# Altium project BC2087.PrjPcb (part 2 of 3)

## Sheet BOOT_JTAG_AUX.SchDoc: =project_title
size Tabloid; CompanyName: Luxonis Holding; DrawnBy: Boris Chou / Blaz Kvas; Organization: Luxonis Holding; Address1: 1925 Harmony Park Drive; Address2: Westminster, CO; Address3: 80234; Address4: United States; DocumentNumber: D2088000; Revision: R1M1E1; SheetNumber: 9; SheetTotal: 12
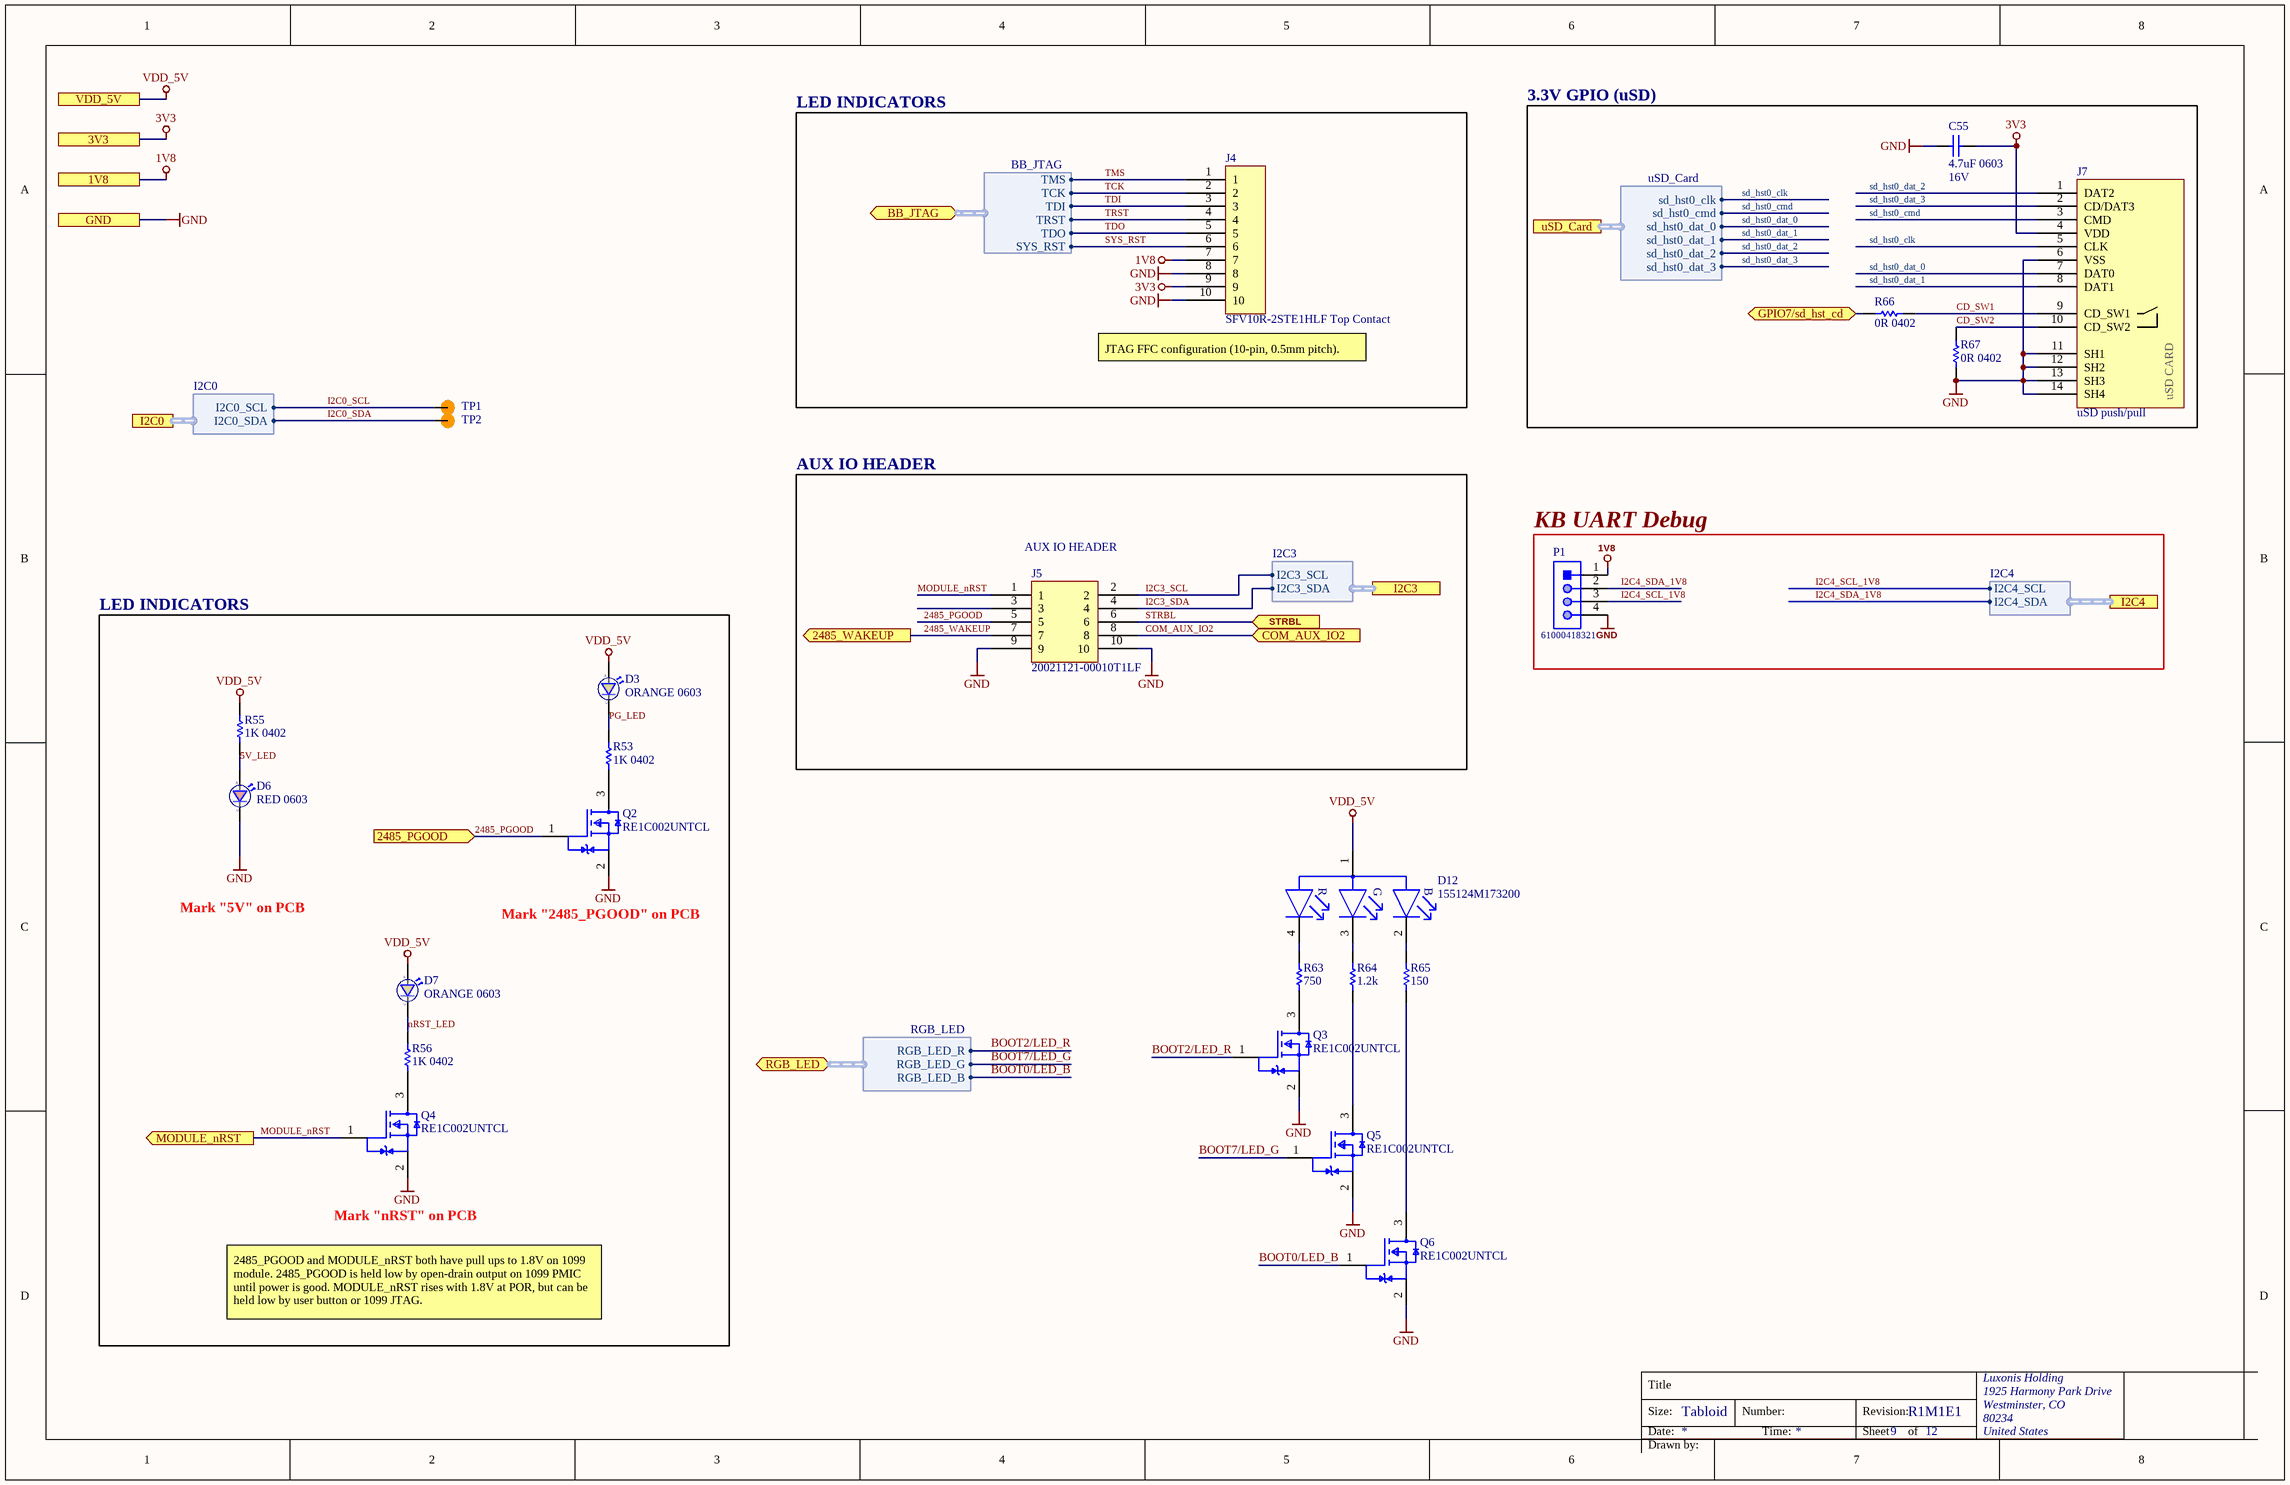
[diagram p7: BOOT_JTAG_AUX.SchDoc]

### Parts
C55  4.7uF 0603  Voltage Rating: 16V  [CAPC0603(1608)100_N]
D3  ORANGE 0603  [SML_D1xx8W]
D6  RED 0603  [SML_D1xx8W]
D7  ORANGE 0603  [SML_D1xx8W]
D12  155124M173200  [FP-155124M173200-MFG]
J4  SFV10R-2STE1HLF Top Contact  [SFV10R-2STE1HLF]
J5  20021121-00010T1LF  [20021121-00010T1LF]
J7  uSD push/pull  [104031-0811]
P1  61000418321  [61000418321]
Q2  RE1C002UNTCL  [RE1C002UNTCL]
Q3  RE1C002UNTCL  [RE1C002UNTCL]
Q4  RE1C002UNTCL  [RE1C002UNTCL]
Q5  RE1C002UNTCL  [RE1C002UNTCL]
Q6  RE1C002UNTCL  [RE1C002UNTCL]
R53  1K 0402  [RESC0402(1005)_N]
R55  1K 0402  [RESC0402(1005)_N]
R56  1K 0402  [RESC0402(1005)_N]
R63  value 750  [RESC1005X40X25NL05T05]  (hidden comment: ERJ2RKF7500X)
R64  value 1.2k  [RESC1005X40X25NL05T05]  (hidden comment: CRCW04021K20FKED)
R65  value 150  [RESC1005X40X25NL05T10]  (hidden comment: RC0402FR-07150RL)
R66  0R 0402  [RESC0402(1005)_N]
R67  0R 0402  [RESC0402(1005)_N]
TP1  TP100_200_NS  [TP100_200_NS]  (value not drawn)  (no BOM)
TP2  TP100_200_NS  [TP100_200_NS]  (value not drawn)  (no BOM)

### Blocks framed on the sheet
LED INDICATORS: J4
3.3V GPIO (uSD): C55 J7 R66 R67
AUX IO HEADER: J5
KB UART Debug: P1
LED INDICATORS: D3 D6 D7 Q2 Q4 R53 R55 R56

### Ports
1V8, 3V3, 2485_PGOOD (in), 2485_WAKEUP (out), BB_JTAG (bidir, harness BB_JTAG), COM_AUX_IO2 (in), GND, GPIO7/sd_hst_cd (bidir), I2C0 (harness I2C0), I2C3 (harness I2C3), I2C4 (harness I2C4), MODULE_nRST (out), RGB_LED (bidir, harness RGB_LED), STRBL (in), uSD_Card (harness uSD_Card), VDD_5V

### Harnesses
BB_JTAG: TMS, TCK, TDI, TRST, TDO, SYS_RST
I2C3: I2C3_SDA, I2C3_SCL
uSD_Card: sd_hst0_clk, sd_hst0_cmd, sd_hst0_dat_0, sd_hst0_dat_1, sd_hst0_dat_2, sd_hst0_dat_3
I2C0: I2C0_SDA, I2C0_SCL
RGB_LED: RGB_LED_G, RGB_LED_B, RGB_LED_R
I2C4: I2C4_SDA, I2C4_SCL

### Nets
1V8: J4.7 P1.1 ; port 1V8
3V3: C55.2 J4.9 J7.4(VDD) ; port 3V3
GND: C55.1 D6.1(C) J4.8 J4.10 J5.9 J5.10 J7.6(VSS) J7.11(SH1) J7.12(SH2) J7.13(SH3) J7.14(SH4) P1.4 Q2.2(Source) Q3.2(Source) Q4.2(Source) Q5.2(Source) Q6.2(Source) R67.1 ; port GND
VDD_5V: D3.2(A) D7.2(A) D12.1(COMMON_ANODE) R55.2 ; port VDD_5V
5V_LED: D6.2(A) R55.1
2485_PGOOD: J5.5 Q2.1(Gate) ; port 2485_PGOOD
2485_WAKEUP: J5.7 ; port 2485_WAKEUP
BOOT0/LED_B: Q6.1(Gate) ; port RGB_LED.RGB_LED_B
BOOT2/LED_R: Q3.1(Gate) ; port RGB_LED.RGB_LED_R
BOOT7/LED_G: Q5.1(Gate) ; port RGB_LED.RGB_LED_G
CD_SW1: J7.9(CD_SW1) R66.1
CD_SW2: J7.10(CD_SW2) R67.2
COM_AUX_IO2: J5.8 ; port COM_AUX_IO2
GPIO7/sd_hst_cd: R66.2 ; port GPIO7/sd_hst_cd
I2C0_SCL: TP1.1 ; port I2C0.I2C0_SCL
I2C0_SDA: TP2.1 ; port I2C0.I2C0_SDA
I2C3_SCL: J5.2 ; port I2C3.I2C3_SCL
I2C3_SDA: J5.4 ; port I2C3.I2C3_SDA
I2C4_SCL_1V8: P1.3 ; port I2C4.I2C4_SCL
I2C4_SDA_1V8: P1.2 ; port I2C4.I2C4_SDA
MODULE_nRST: J5.1 Q4.1(Gate) ; port MODULE_nRST
nRST_LED: D7.1(C) R56.2
PG_LED: D3.1(C) R53.2
sd_hst0_clk: J7.5(CLK) ; port uSD_Card.sd_hst0_clk
sd_hst0_cmd: J7.3(CMD) ; port uSD_Card.sd_hst0_cmd
sd_hst0_dat_0: J7.7(DAT0) ; port uSD_Card.sd_hst0_dat_0
sd_hst0_dat_1: J7.8(DAT1) ; port uSD_Card.sd_hst0_dat_1
sd_hst0_dat_2: J7.1(DAT2) ; port uSD_Card.sd_hst0_dat_2
sd_hst0_dat_3: J7.2(CD/DAT3) ; port uSD_Card.sd_hst0_dat_3
STRBL: J5.6 ; port STRBL
SYS_RST: J4.6 ; port BB_JTAG.SYS_RST
TCK: J4.2 ; port BB_JTAG.TCK
TDI: J4.3 ; port BB_JTAG.TDI
TDO: J4.5 ; port BB_JTAG.TDO
TMS: J4.1 ; port BB_JTAG.TMS
TRST: J4.4 ; port BB_JTAG.TRST
NetD12_2: D12.2(BLUE_C) R65.2
NetD12_3: D12.3(GREEN_C) R64.2
NetD12_4: D12.4(RED_C) R63.2
NetQ2_3: Q2.3(Drain) R53.1
NetQ3_3: Q3.3(Drain) R63.1
NetQ4_3: Q4.3(Drain) R56.1
NetQ5_3: Q5.3(Drain) R64.1
NetQ6_3: Q6.3(Drain) R65.1

Not connected (* = marked no-connect by the designer): J5 3

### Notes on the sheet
- (near J4) JTAG FFC configuration (10-pin, 0.5mm pitch).
- (near J5) AUX IO HEADER
- Mark "5V" on PCB
- Mark "2485_PGOOD" on PCB
- Mark "nRST" on PCB
- 2485_PGOOD and MODULE_nRST both have pull ups to 1.8V on 1099 module. 2485_PGOOD is held low by open-drain output on 1099 PMIC until power is good. MODULE_nRST rises with 1.8V at POR, but can be held low by user button or 1099 JTAG.

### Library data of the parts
C55 = GRM188R61C475KAAJD: CAP CER 4.7UF 16V X5R 0603 10%; Manufacturer 1: Murata; Material: Ceramic
D3 D7 = SML-D12D8WT86: LED ORANGE DIFFUSED 0603 SMD Orange 605nm LED Indication - Discrete 2.2V 0603 (1608 Metric); Manufacturer 1: Rohm; Lens Color: White; Lens Style: Diffused,Colorless,Rectangular; Number of LEDs: 1; Viewing Angle: 160°; Forward Current: 20mA; Luminous Intensity: 100mcd
D6 = SML-D12U8WT86: LED RED DIFFUSED 0603 SMD Red 620nm LED Indication - Discrete 2.2V 0603 (1608 Metric); Manufacturer 1: Rohm; Lens Color: White,Clear,Diffused; Lens Style: Rectangular,Diffused,Colorless; Forward Current: 20mA; Luminous Intensity: 63mcd; Number of LEDs: 1; Viewing Angle: 160°
D12 = CMP-007-00038-1: Triple Color LED; Manufacturer 1: Wurth Elektronik; Max Current Rating: 30mA; Viewing Angle: 120°; Colour: RGB; Lens Style: Side lens; Forward Current: 20mA
J4 = SFV10R-2STE1HLF: CONN FFC TOP 10POS 0.50MM R/A; Manufacturer 1: Amphenol FCI; Actuator Material: Glass,Polyphenylene; Number of Contacts: 10; Current Rating: 500mA; Voltage Rating: 50V; Contact Resistance: 30mR; Insulation Resistance: 100MR; Gender: Female; Wire/Cable Type: Straight; Pitch: 0.5mm; System: Connector
J5 = 20021121-00010T1LF: CONN HEADER SMD 10POS 1.27MM; Manufacturer 1: Amphenol FCI; Number of Contacts: 10; Contact Resistance: 30mR; Max Voltage Rating (AC): 125V; Connector Type: Male Pin; Row Spacing: 0.05inch
J7 = 104031-0811: CONN MICRO SD CARD PUSH-PULL R/A; Manufacturer 1: Molex
P1 = CMP-002-00148-1: Terminal and Terminal Block; Manufacturer 1: Wurth Elektronik; Connector Type: BOARD CONNECTOR
Q2-Q6 = RE1C002UNTCL: MOSFET N-CH 20V 0.2A EMT3; Manufacturer 1: Rohm; Continuous Drain Current (ID): 200mA; Rds On Max: 1.2R; Input Capacitance: 25pF; Max Power Dissipation: 150mW
R53 R55 R56 = RC0402FR-071KL: RES SMD 1K OHM 1% 1/16W 0402 1 kOhms ±1% 0.063W, 1/16W Chip Resistor 0402 (1005 Metric) Moisture Resistant Thick Film; Manufacturer 1: Yageo; Temperature Coefficient: 100ppm/°C; Power Rating: 62.5mW; Voltage Rating (DC): 50V; Resistance: 1kR
R63 = CMP-009-00197-1: Fixed Resistor, Metal Glaze/thick Film, 0.1W, 750ohm, 50V, 1% +/-Tol, 100ppm/Cel, Surface Mount, 0402; Manufacturer 1: Panasonic; Power: 100mW
R64 = CMP-009-00198-1: Fixed Resistor, Metal Glaze/thick Film, 0.063W, 1200ohm, 50V, 1% +/-Tol, 100ppm/Cel, Surface Mount, 0402; Manufacturer 1: Vishay; Power: 63mW
R65 = CMP-009-00196-1: Fixed Resistor, Metal Glaze/thick Film, 0.0625W, 150ohm, 50V, 1% +/-Tol, 100ppm/Cel, Surface Mount, 0402; Manufacturer 1: Yageo
R66 R67 = CRCW04020000Z0ED: RES SMD 0 OHM JUMPER 1/16W 0402; Manufacturer 1: Vishay; Resistance: 0mR; Power Rating: 63mW; Voltage Rating: 50V; Temperature Coefficient: 100ppm/°C; Tolerance: 5%
TP1 TP2 = TEST_POINT

## Sheet PoE_Si3404.SchDoc: =project_title
size Tabloid; CompanyName: Luxonis Holding; DrawnBy: Boris Chou / Blaz Kvas; Organization: Luxonis Holding; Address1: 1925 Harmony Park Drive; Address2: Westminster, CO; Address3: 80234; Address4: United States; DocumentNumber: D2088000; Revision: R1M1E1; SheetNumber: 3; SheetTotal: 12
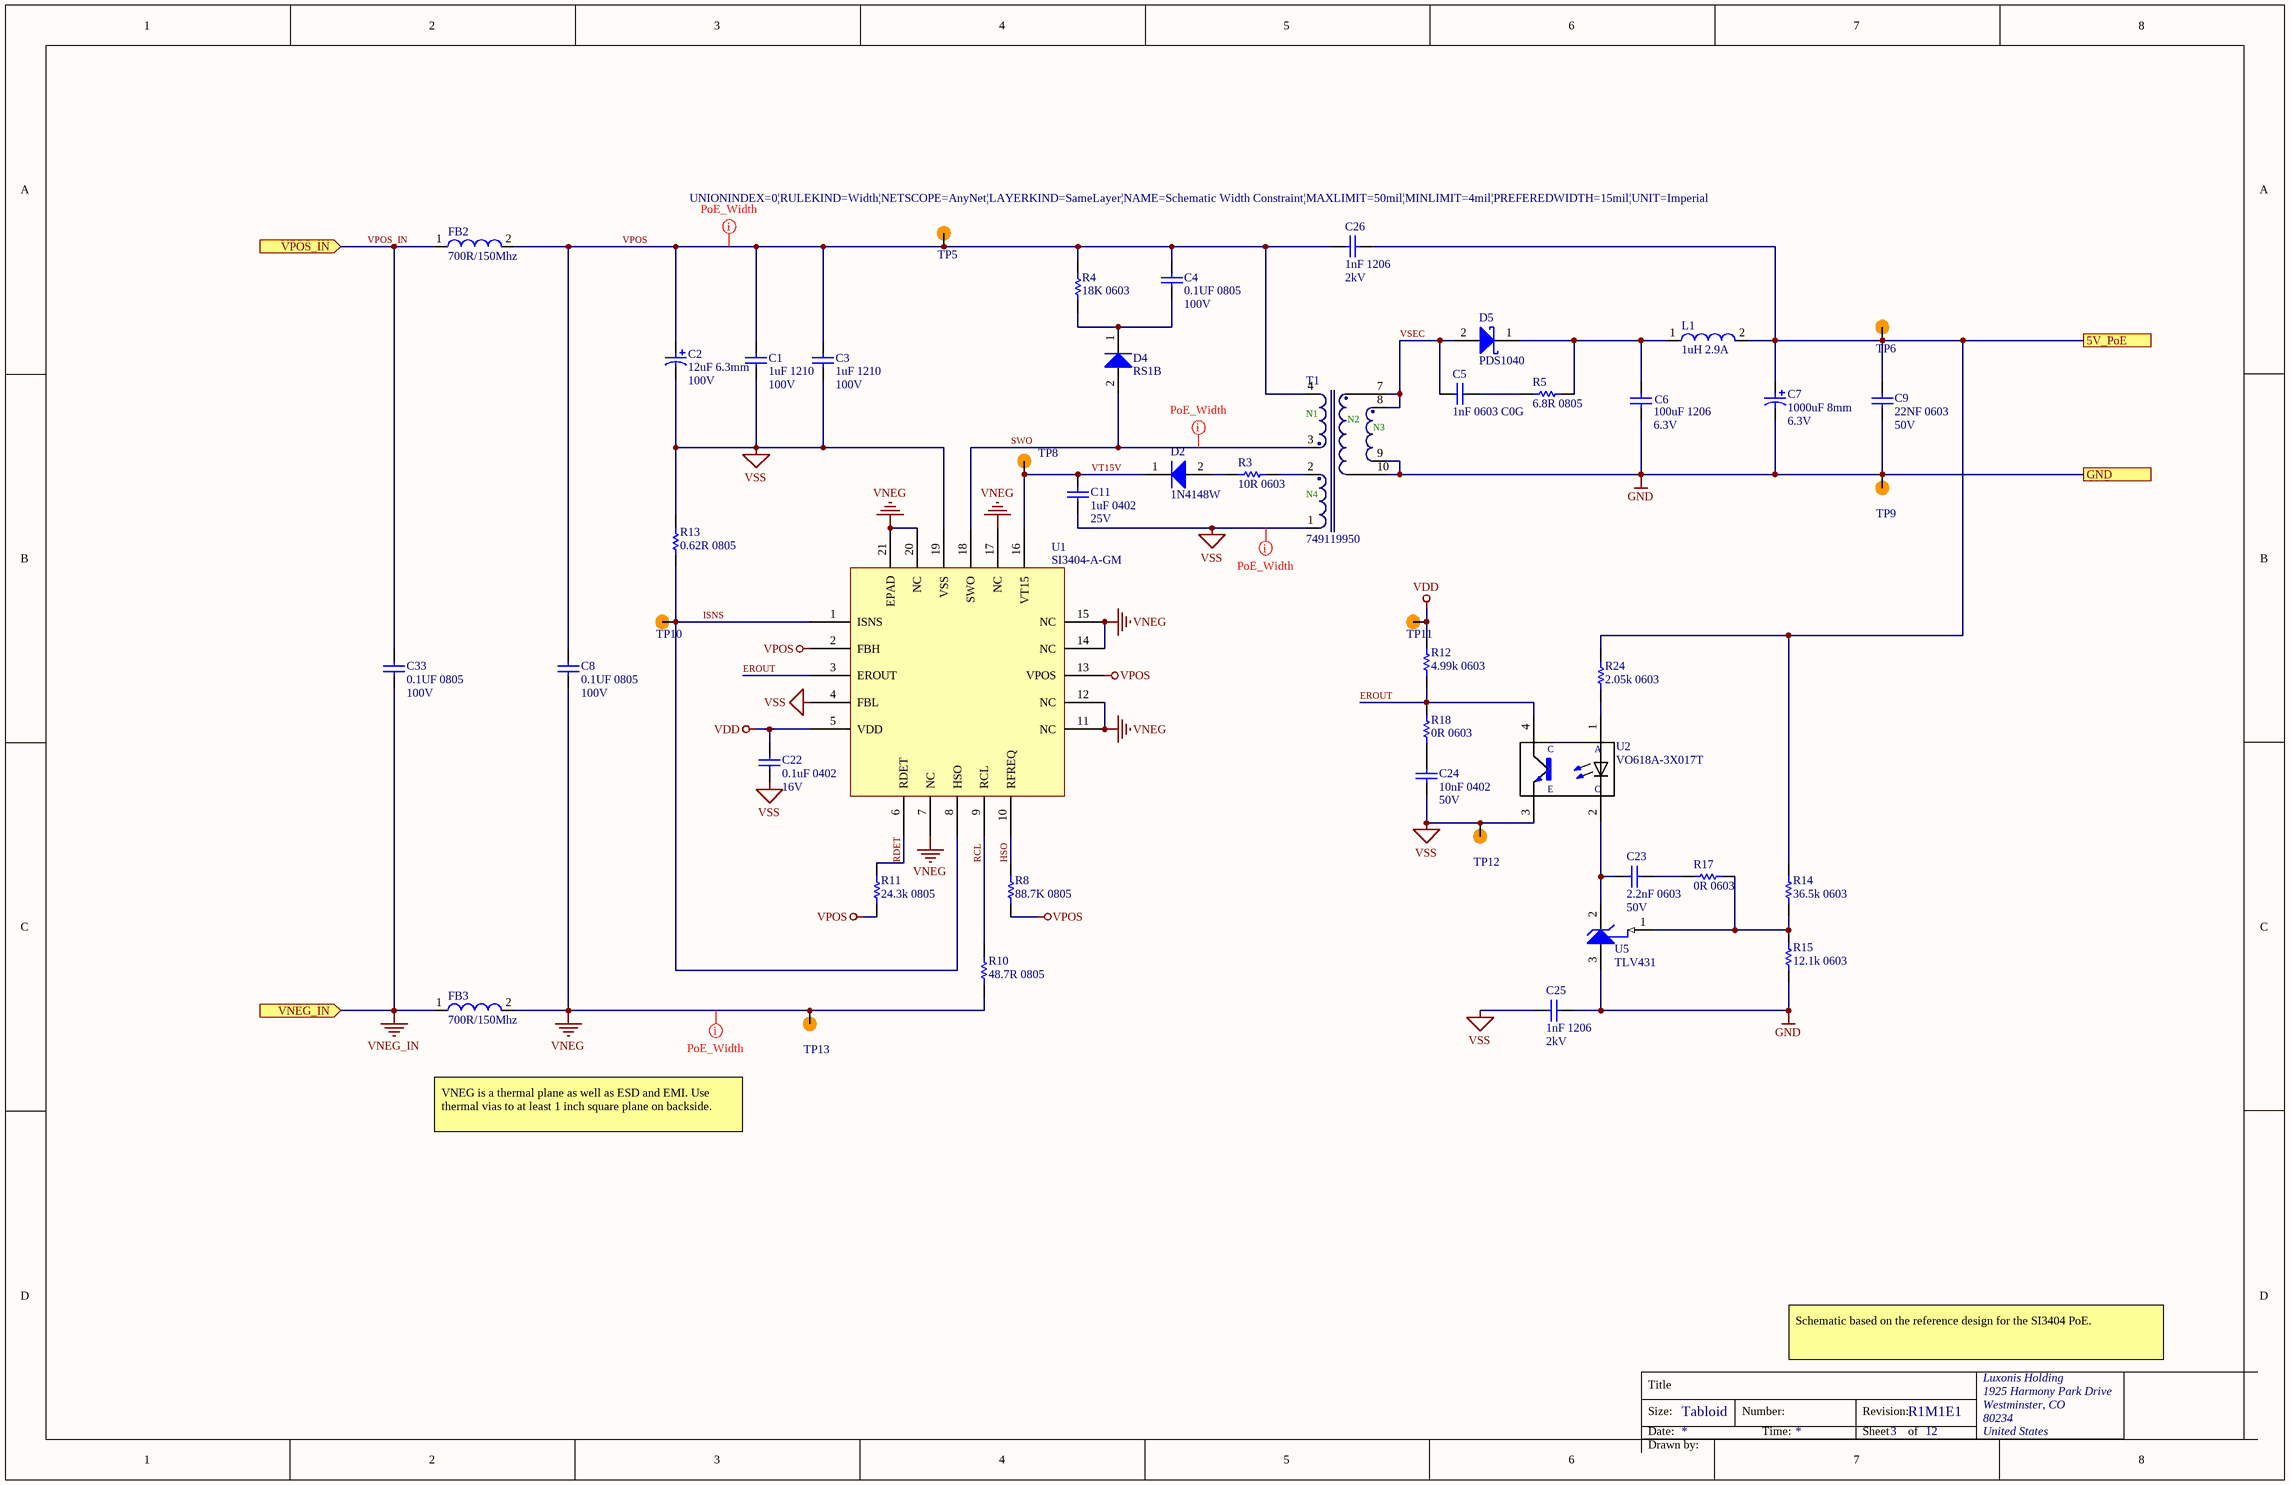
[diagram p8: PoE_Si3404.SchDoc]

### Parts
C1  1uF 1210  Voltage Rating: 100V  [CAPC1210(3225)280_N]
C2  12uF 6.3mm  Voltage: 100V  [EEU-FC2A120]
C3  1uF 1210  Voltage Rating: 100V  [CAPC1210(3225)280_N]
C4  0.1UF 0805  Voltage Rating: 100V  [CAPC0805(2012)145_N]
C5  1nF 0603 C0G  [CAPC0603(1608)100_N]
C6  100uF 1206  Voltage: 6.3V  [CAPC1206(3216)190_N]
C7  1000uF 8mm  Voltage: 6.3V  [ECA-0JM102]
C8  0.1UF 0805  Voltage Rating: 100V  [CAPC0805(2012)145_N]
C9  22NF 0603  Voltage: 50V  [CAPC0603(1608)100_N]
C11  1uF 0402  Voltage Rating: 25V  [CAPC0402(1005)70_N]
C22  0.1uF 0402  Voltage Rating: 16V  [CAPC0402(1005)60_N]
C23  2.2nF 0603  Voltage: 50V  [CAPC0603(1608)100_N]
C24  10nF 0402  Voltage Rating: 50V  [CAPC0402(1005)60_N]
C25  1nF 1206  Voltage Rating (DC): 2kV  [CAPC1206(3216)190_N]
C26  1nF 1206  Voltage Rating (DC): 2kV  [CAPC1206(3216)190_N]
C33  0.1UF 0805  Voltage Rating: 100V  [CAPC0805(2012)145_N]
D2  1N4148W  [1N4148W-7-F]
D4  RS1B  [RS1B]
D5  PDS1040  [PDS1040-13]
FB2  700R/150Mhz  [742792040]
FB3  700R/150Mhz  [742792040]
L1  1uH 2.9A  [DO1608C-102MLx]
R3  10R 0603  [RESC0603(1608)_N]
R4  18K 0603  [RESC0603(1608)_N]
R5  6.8R 0805  [RESC0805(2012)_N]
R8  88.7K 0805  [RESC0805(2012)_N]
R10  48.7R 0805  [RESC0805(2012)_N]
R11  24.3k 0805  [RESC0805(2012)_N]
R12  4.99k 0603  [RESC0603(1608)_N]
R13  0.62R 0805  [RESC0805(2012)_N]
R14  36.5k 0603  [RESC0603(1608)_N]
R15  12.1k 0603  [RESC0603(1608)_N]
R17  0R 0603  [RESC0603(1608)_N]
R18  0R 0603  [RESC0603(1608)_N]
R24  2.05k 0603  [RESC0603(1608)_N]
T1  749119950  [749119950]
TP5  TP100_200_NS  [TP100_200_NS]  (value not drawn)  (no BOM)
TP6  TP100_200_NS  [TP100_200_NS]  (value not drawn)  (no BOM)
TP8  TP100_200_NS  [TP100_200_NS]  (value not drawn)  (no BOM)
TP9  TP100_200_NS  [TP100_200_NS]  (value not drawn)  (no BOM)
TP10  TP100_200_NS  [TP100_200_NS]  (value not drawn)  (no BOM)
TP11  TP100_200_NS  [TP100_200_NS]  (value not drawn)  (no BOM)
TP12  TP100_200_NS  [TP100_200_NS]  (value not drawn)  (no BOM)
TP13  TP100_200_NS  [TP100_200_NS]  (value not drawn)  (no BOM)
U1  SI3404-A-GM  [Si3404-A-GM]
U2  VO618A-3X017T  [VO618A-3X017T]
U5  TLV431  [TLV431BCDBZR]

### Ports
5V_PoE, GND, VNEG_IN (in), VPOS_IN (in)

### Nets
5V_PoE: C7.1 C9.2 C26.2 L1.2 R14.2 R24.2 TP6.1 ; port 5V_PoE
GND: C6.1 C7.2 C9.1 C25.2 R15.1 T1.9 T1.10 TP9.1 U5.3(ANODE) ; port GND
VDD: C22.2 R12.2 TP11.1 U1.5(VDD)
VNEG: C8.1 FB3.2 R10.1 TP13.1 U1.7(NC) U1.11(NC) U1.12(NC) U1.14(NC) U1.15(NC) U1.17(NC) U1.20(NC) U1.21(EPAD)
VNEG_IN: C33.1 FB3.1 ; port VNEG_IN
VPOS: C1.2 C2.1 C3.2 C4.2 C8.2 C26.1 FB2.2 R4.2 R8.1 R11.1 T1.4 TP5.1 U1.2(FBH) U1.13(VPOS)
VSS: C1.1 C2.2 C3.1 C11.1 C22.1 C24.1 C25.1 R13.2 T1.1 TP12.1 U1.4(FBL) U1.19(VSS) U2.3(E)
EROUT: R12.1 R18.2 U1.3(EROUT) U2.4(CO)
HSO: R8.2 U1.10(RFREQ)
ISNS: R13.1 TP10.1 U1.1(ISNS) U1.8(HSO)
RCL: R10.2 U1.9(RCL)
RDET: R11.2 U1.6(RDET)
SWO: D4.2(A) T1.3 U1.18(SWO)
VPOS_IN: C33.2 FB2.1 ; port VPOS_IN
VSEC: C5.2 D5.2(A) T1.7 T1.8
VT15V: C11.2 D2.1(K) TP8.1 U1.16(VT15)
NetC4_1: C4.1 D4.1(K) R4.1
NetC5_1: C5.1 R5.1
NetC6_2: C6.2 D5.1(K) L1.1 R5.2
NetC23_1: C23.1 U2.2(C) U5.2(CATHODE)
NetC23_2: C23.2 R17.2
NetC24_2: C24.2 R18.1
NetD2_2: D2.2(A) R3.1
NetR3_2: R3.2 T1.2
NetR14_1: R14.1 R15.2 R17.1 U5.1(REF)
NetR24_1: R24.1 U2.1(A)

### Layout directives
rule Width Constraint [Pref Width = 15mil    Min Width = 4mil    Max Width = 50mil]; net class PoE: SWO, VNEG, VPOS, VSS

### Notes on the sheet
- VNEG is a thermal plane as well as ESD and EMI. Use thermal vias to at least 1 inch square plane on backside.
- Schematic based on the reference design for the SI3404 PoE.

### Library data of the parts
C1 C3 = CL32B105KCJNNNE: CAP CER 1UF 100V X7R 1210; Manufacturer 1: Samsung; Tolerance: 10%
C2 = EEU-FC2A120: CAP ALUM 12UF 20% 100V RADIAL; Manufacturer 1: Panasonic; Lead/Base Style: Straight; Ripple Current: 114mA; Life (Hours): 1000Hour; ESR (Equivalent Series Resistance): 1.8R; Leakage Current: 3uA; Dissipation Factor: 0.07%; Polarity: Polar; Lead Diameter: 0.5mm
C4 C8 C33 = CL21B104KCFNNNE: CAP CER 0.1UF 100V X7R 0805; Manufacturer 1: Samsung; Tolerance: 10%; Capacitance: 100nF
C5 = GRM1885C1H102FA01D: CAP CER 1000PF 50V C0G/NP0 0603; Manufacturer: Murata; Material: Ceramic; Tolerance: 1%; Temperature Coefficient: 30ppm/°C
C6 = CL31A107MQHNNNE: CAP CER 100UF 6.3V X5R 1206; Manufacturer 1: Samsung; Material: Ceramic; Tolerance: 20%
C7 = ECA-0JM102: CAP ALUM 1000UF 20% 6.3V RADIAL; Manufacturer 1: Panasonic; Capacitance: 1mF; Ripple Current: 580mA; Life (Hours): 2000Hour; Dissipation Factor: 0.28%; Lead/Base Style: Straight; Polarity: Polar; Leakage Current: 3uA; Lead Diameter: 0.6mm
C9 = C0603C223K5RACTU: CAP CER 0.022UF 50V X7R 0603; Manufacturer 1: KEMET; Dielectric Material: Ceramic; Tolerance: 10%; Dissipation Factor: 2.5%
C11 = GRM155R61E105KA12D: CAP CER 1UF 25V X5R 0402 10%; Manufacturer 1: Murata; Material: Ceramic
C22 = CL05B104KO5NFNC: CAP CER 0.1UF 16V X7R 0402; Manufacturer 1: Samsung; Tolerance: 10%; Capacitance: 100nF
C23 = GRM1885C1H222JA01D: CAP CER 2200PF 50V C0G/NP0 0603; Manufacturer 1: Murata; Dielectric Material: Ceramic; Tolerance: 5%; Dielectric: C0G; Temperature Coefficient: 30ppm/°C; Insulation Resistance: 10GR
C24 = GRM155R71H103KA88D: CAP CER 10000PF 50V X7R 0402; Manufacturer 1: Murata; Material: Ceramic; Tolerance: 10%; Voltage: 25V
C25 C26 = C1206C102KGRACTU: CAP CER 1000PF 2KV X7R 1206; Manufacturer 1: KEMET; Dielectric Material: Ceramic; Tolerance: 10%
D2 = 1N4148W-7-F: DIODE GEN PURP 100V 300MA SOD123; Manufacturer 1: Diodes; Element Configuration: Single; Forward Current: 150mA; Forward Voltage: 1.25V; Reverse Recovery Time: 4ns; Peak Non-Repetitive Surge Current: 2A; Peak Reverse Current: 1uA; Power Dissipation: 400mW; Polarity: Standard; Voltage Rating (DC): 75V; Capacitance: 2pF; Current: 15A
D4 = RS1B: DIODE GEN PURP 100V 1A SMA; Manufacturer 1: ON Semiconductor / Fairchild; Reverse Recovery Time: 150ns; Element Configuration: Single; Peak Reverse Current: 5uA; Peak Non-Repetitive Surge Current: 30A; Forward Voltage: 1.3V; Polarity: Standard; Capacitance: 10pF; Power Dissipation: 1.19W
D5 = PDS1040-13: DIODE SCHOTTKY 40V 10A POWERDI5; Manufacturer 1: Diodes; Element Configuration: Common Anode; Peak Reverse Current: 700uA; Peak Non-Repetitive Surge Current: 275A; Forward Voltage: 510mV; Polarity: Standard
FB2 FB3 = 742792040: FERRITE BEAD 600 OHM 0805 1LN; Manufacturer 1: Wurth Electronics; Current Rating: 2A; Inductance: 5.6H; Tolerance: 25%; Impedance: 600R; Number of Lines: 1; DC Resistance (DCR): 150mR; Test Frequency: 100MHz
L1 = DO1608C-102ML: IND POWER WIREWOUND 1uH 20% 100KHz FERRITE 2.7A; Manufacturer 1: Coilcraft; Manufacturer Part Number 1: DO1608C-102MLC; Self Resonant Frequency: 130MHz; DC Resistance (DCR): 50mR
R3 = CRCW060310R0FKEA: RES SMD 10 OHM 1% 1/10W 0603; Manufacturer 1: Vishay; Power Rating: 100mW; Temperature Coefficient: 100ppm/°C; Voltage Rating: 75V
R4 = RC0603JR-0718KL: RES SMD 18K OHM 5% 1/10W 0603; Manufacturer 1: Yageo; Resistance: 18kR; Power Rating: 100mW; Temperature Coefficient: 100ppm/°C; Voltage Rating: 75V; Voltage Rating (DC): 50V
R5 = RC0805FR-076R8L: RES SMD 6.8 OHM 1% 1/8W 0805; Manufacturer 1: Yageo; Voltage Rating: 150V; Power Rating: 125mW; Temperature Coefficient: 200ppm/°C
R8 = CRCW080588K7FKEA: RES SMD 88.7K OHM 1% 1/8W 0805; Manufacturer 1: Vishay; Resistance: 88.7kR; Temperature Coefficient: 100ppm/°C; Max Power Dissipation: 125mW; Voltage Rating (DC): 150V
R10 = RC0805FR-0748R7L: RES SMD 48.7 OHM 1% 1/8W 0805; Manufacturer 1: Yageo; Temperature Coefficient: 100ppm/°C; Power Rating: 125mW; Voltage Rating: 150V
R11 = CRCW080524K3FKEA: RES SMD 24.3K OHM 1% 1/8W 0805; Manufacturer 1: Vishay; Resistance: 24.3kR; Temperature Coefficient: 100ppm/°C; Power Rating: 125mW; Voltage Rating: 150V
R12 = RC0603FR-074K99L: RES SMD 4.99K OHM 1% 1/10W 0603; Manufacturer 1: Yageo; Resistance: 4.99kR; Temperature Coefficient: 100ppm/°C; Voltage Rating (DC): 50V; Power Rating: 100mW; Voltage Rating: 75V
R13 = RL0805FR-070R62L: RES SMD 620 MOHM 1% 1/8W 0805; Manufacturer 1: Yageo; Resistance: 620mR; Power Rating: 125mW; Temperature Coefficient: 200ppm/°C; Voltage Rating (DC): 300V
R14 = RC0603FR-0736K5L: RES SMD 36.5K OHM 1% 1/10W 0603; Manufacturer 1: Yageo; Resistance: 36.5kR; Power Rating: 100mW; Voltage Rating: 50V; Temperature Coefficient: 100ppm/°C; Working Voltage: 75V
R15 = RC0603FR-0712K1L: RES SMD 12.1K OHM 1% 1/10W 0603; Manufacturer 1: Yageo; Power Rating: 100mW; Temperature Coefficient: 100ppm/°C; Resistance: 12.1kR; Voltage Rating: 50V
R17 R18 = CRCW06030000Z0EA: RES SMD 0 OHM JUMPER 1/10W 0603 0 Ohms Jumper 0.1W, 1/10W Chip Resistor 0603 (1608 Metric) Automotive AEC-Q200 Thick Film; Manufacturer 1: Vishay; Manufacturer Part Number 1: CRCW0603-0000Z0EA; Resistance: 0mR; Power Rating: 100mW; Voltage Rating: 75V; Temperature Coefficient: 100ppm/°C; Tolerance: 5%; Current Rating: 2A
R24 = RC0603FR-072K05L: RES SMD 2.05K OHM 1% 1/10W 0603; Manufacturer 1: Yageo; Resistance: 2.05kR; Power Rating: 100mW; Voltage Rating: 50V; Temperature Coefficient: 100ppm/°C
T1 = 749119950: TRANS FLYBACK POE 127UH SMD; Manufacturer 1: Wurth Electronics; Current Rating: 1.3A; Power Rating: 13W; Max Input Voltage: 57V; Min Input Voltage: 36V; Output Voltage: 5V; Frequency: 500kHz
TP5 TP6 TP8-TP13 = TEST_POINT
U1 = SI3404-A-GM: IC POE CNTRL 1 CHANNEL 20QFN; Manufacturer 1: Silicon Labs
U2 = VO618A-3X017T: OPTOISOLATOR 5.3KV TRANS 4-SMD; Manufacturer 1: Vishay Semiconductors; Max Power Dissipation: 150mW; Collector Emitter Voltage (VCEO): 80V; Collector Emitter Saturation Voltage: 400mV; Max Collector Current: 50mA; Max Input Current: 60mA; Number of Channels: 1; Reverse Breakdown Voltage: 6V; Forward Voltage: 1.1V; Current Transfer Ratio: 100%
U5 = TLV431BCDBZR: IC VREF SHUNT ADJ SOT23-3; Manufacturer 1: Texas Instruments; Tolerance: 0.5%; Max Input Voltage: 7V; Output Voltage: 6V; Max Output Current: 15mA; Temperature Coefficient: 129ppm/°C; Cathode Current: 100uA; Reference Type: Shunt,Adjustable; Number of Channels: 1; Min Input Voltage: 1.24V

## Sheet POWER_GEN.SchDoc: =project_title
size Tabloid; CompanyName: Luxonis Holding; DrawnBy: Boris Chou / Blaz Kvas; Organization: Luxonis Holding; Address1: 1925 Harmony Park Drive; Address2: Westminster, CO; Address3: 80234; Address4: United States; DocumentNumber: D2088000; Revision: R1M1E1; SheetNumber: 12; SheetTotal: 12
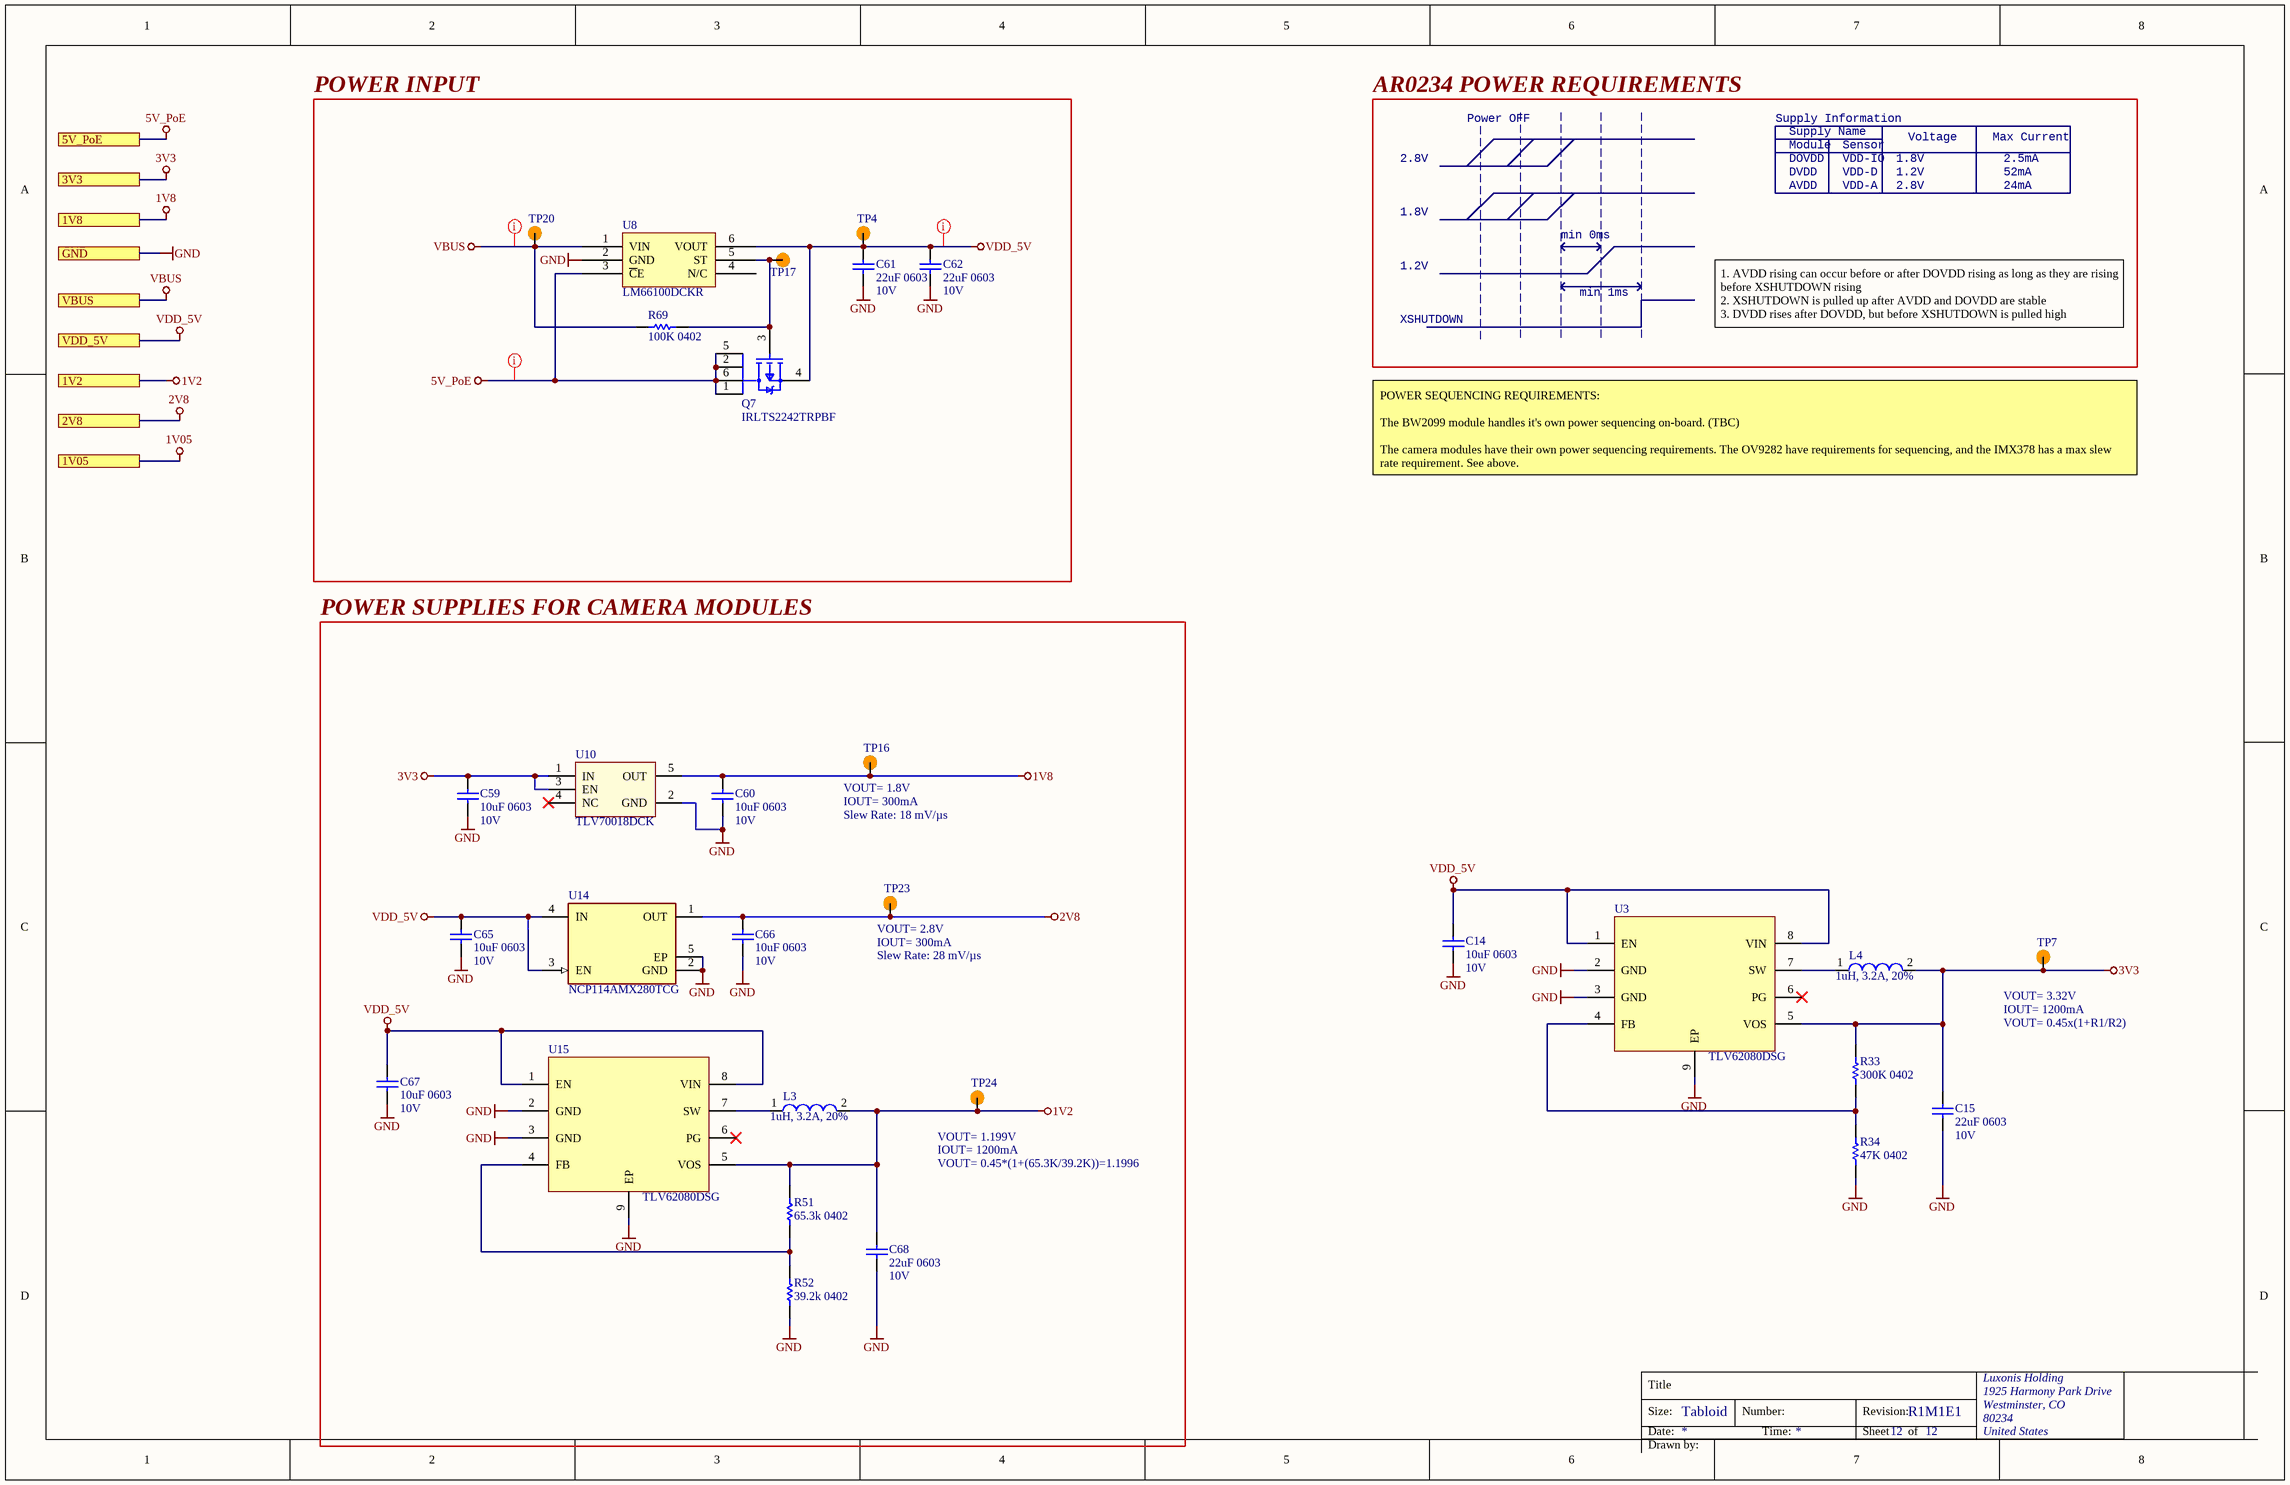
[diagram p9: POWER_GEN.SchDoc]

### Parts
C14  10uF 0603  Voltage Rating: 10V  [CAPC0603(1608)100_L]
C15  22uF 0603  Voltage Rating: 10V  [CAPC0603(1608)100_L]
C59  10uF 0603  Voltage Rating: 10V  [CAPC0603(1608)100_N]
C60  10uF 0603  Voltage Rating: 10V  [CAPC0603(1608)100_N]
C61  22uF 0603  Voltage Rating: 10V  [CAPC0603(1608)100_L]
C62  22uF 0603  Voltage Rating: 10V  [CAPC0603(1608)100_L]
C65  10uF 0603  Voltage Rating: 10V  [CAPC0603(1608)100_L]
C66  10uF 0603  Voltage Rating: 10V  [CAPC0603(1608)100_L]
C67  10uF 0603  Voltage Rating: 10V  [CAPC0603(1608)100_L]
C68  22uF 0603  Voltage Rating: 10V  [CAPC0603(1608)100_L]
L3  1uH, 3.2A, 20%  [DFE252012P-1R0M=P2]
L4  1uH, 3.2A, 20%  [DFE252012P-1R0M=P2]
Q7  IRLTS2242TRPBF  [TSOP-6-MFG]
R33  300K 0402  [RESC0402(1005)_L]
R34  47K 0402  [RESC0402(1005)_L]
R51  65.3k 0402  [RESC0402(1005)_L]
R52  39.2k 0402  [RESC0402(1005)_L]
R69  100K 0402  [RESC0402(1005)_L]
TP4  TP100_200_NS  [TP100_200_NS]  (value not drawn)  (no BOM)
TP7  TP100_200_NS  [TP100_200_NS]  (value not drawn)  (no BOM)
TP16  TP100_200_NS  [TP100_200_NS]  (value not drawn)  (no BOM)
TP17  TP100_200_NS  [TP100_200_NS]  (value not drawn)  (no BOM)
TP20  TP100_200_NS  [TP100_200_NS]  (value not drawn)  (no BOM)
TP23  TP100_200_NS  [TP100_200_NS]  (value not drawn)  (no BOM)
TP24  TP100_200_NS  [TP100_200_NS]  (value not drawn)  (no BOM)
U3  TLV62080DSG  [TLV62080DSG]
U8  LM66100DCKR  [LM66100DCKR]
U10  TLV70018DCK  [TLV70018DCK]
U14  NCP114AMX280TCG  [FP-517CU-MFG]
U15  TLV62080DSG  [TLV62080DSG]

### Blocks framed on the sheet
POWER INPUT: C61 C62 Q7 R69 TP4 TP17 TP20 U8
POWER SUPPLIES FOR CAMERA MODULES: C59 C60 C65-C68 L3 R51 R52 TP16 TP23 TP24 U10 U14 U15

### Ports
1V2, 1V05, 1V8, 2V8, 3V3, 5V_PoE, GND, VBUS, VDD_5V

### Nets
1V2: C68.2 L3.2 R51.2 TP24.1 U15.5(VOS) ; port 1V2
1V8: C60.2 TP16.1 U10.5(OUT) ; port 1V8
2V8: C66.2 TP23.1 U14.1(OUT) ; port 2V8
3V3: C15.2 C59.2 L4.2 R33.2 TP7.1 U3.5(VOS) U10.1(IN) U10.3(EN) ; port 3V3
5V_PoE: Q7.1(D) Q7.2(D) Q7.5(D) Q7.6(D) U8.3(~{C}E) ; port 5V_PoE
GND: C14.1 C15.1 C59.1 C60.1 C61.2 C62.2 C65.1 C66.1 C67.1 C68.1 R34.1 R52.1 U3.2(GND) U3.3(GND) U3.9(EP) U8.2(GND) U10.2(GND) U14.2(GND) U14.5(EP) U15.2(GND) U15.3(GND) U15.9(EP) ; port GND
VBUS: R69.2 TP20.1 U8.1(VIN) ; port VBUS
VDD_5V: C14.2 C61.1 C62.1 C65.2 C67.2 Q7.4(S) TP4.1 U3.1(EN) U3.8(VIN) U8.6(VOUT) U14.3(EN) U14.4(IN) U15.1(EN) U15.8(VIN) ; port VDD_5V
NetL3_1: L3.1 U15.7(SW)
NetL4_1: L4.1 U3.7(SW)
NetQ7_3: Q7.3(G) R69.1 TP17.1 U8.5(ST)
NetR33_1: R33.1 R34.2 U3.4(FB)
NetR51_1: R51.1 R52.2 U15.4(FB)

Not connected (* = marked no-connect by the designer): U3 6(PG)*; U8 4(N/C); U10 4(NC)*; U15 6(PG)*

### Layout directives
net class Power_trace: 5V_PoE, VBUS, VDD_5V

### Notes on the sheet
- AR0234 POWER REQUIREMENTS
- 2.8V
- Power OFF
- Supply Information
- DOVDD
- Supply Name
- Module
- VDD-IO
- Sensor
- 1.8V
- Voltage
- Max Current
- 2.5mA
- AVDD
- DVDD
- VDD-A
- VDD-D
- 1.2V
- 24mA
- 52mA
- min 0ms
- min 1ms
- XSHUTDOWN
- 1. AVDD rising can occur before or after DOVDD rising as long as they are rising before XSHUTDOWN rising
  2. XSHUTDOWN is pulled up after AVDD and DOVDD are stable
  3. DVDD rises after DOVDD, but before XSHUTDOWN is pulled high
- POWER SEQUENCING REQUIREMENTS:
  The BW2099 module handles it's own power sequencing on-board. (TBC)
  The camera modules have their own power sequencing requirements. The OV9282 have requirements for sequencing, and the IMX378 has a max slew rate requirement. See above.
- (near TP16) VOUT= 1.8V
- (near TP16) IOUT= 300mA
- (near TP16) Slew Rate: 18 mV/µs
- (near TP23) VOUT= 2.8V
- (near TP23) IOUT= 300mA
- (near TP23) Slew Rate: 28 mV/µs
- (near TP7) VOUT= 3.32V
- (near TP7) IOUT= 1200mA
- VOUT= 0.45x(1+R1/R2)
- (near TP24) VOUT= 1.199V
- (near TP24) IOUT= 1200mA
- VOUT= 0.45*(1+(65.3K/39.2K))=1.1996

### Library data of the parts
C14 C59 C60 C65-C67 = GRM188R61A106ME69D: CAP CER 10UF 10V X5R 0603 20%; Manufacturer 1: Murata; Material: Ceramic
C15 C61 C62 C68 = GRM188R61A226ME15D: CAP CER 22UF 10V X5R 0603 20%; Manufacturer 1: Murata; Material: Ceramic
L3 L4 = DFE252012P-1R0M=P2: FIXED IND 1UH 3.2A 42 MOHM SMD; Manufacturer: Murata; Core Material: Ferrite; Current Rating: 4.3A; Shielding: Shielded; Test Frequency: 1MHz; DC Resistance (DCR): 42mR
Q7 = CMP-016-000020-1: MOSFET P-CH 20V 6.9A 6TSOP; Manufacturer 1: Infineon; Drain to Source Voltage (Vdss): -20V; Rise Time: 18ns; Max Power Dissipation: 2W; Gate to Source Voltage (Vgs): 12V; Input Capacitance: 905pF; Rds On Max: 32mR; Threshold Voltage: -400mV
R33 = RC0402FR-07300KL: RES SMD 300K OHM 1% 1/16W 0402; Manufacturer 1: Yageo; Resistance: 300kR; Temperature Coefficient: 100ppm/°C; Power Rating: 63mW; Voltage Rating: 50V
R34 = RC0402FR-0747KL: RES SMD 47K OHM 1% 1/16W 0402; Manufacturer 1: Yageo; Resistance: 47kR; Power Rating: 62.5mW; Temperature Coefficient: 100ppm/°C; Voltage Rating: 50V; Max Power Dissipation: 63mW
R51 = CRCW040253K6FKED: RES SMD 53.6K OHM 1% 1/16W 0402; Manufacturer 1: Vishay; Resistance: 53.6kR; Temperature Coefficient: 100ppm/°C; Power Rating: 63mW; Voltage Rating: 50V
R52 = CRCW040239K2FKED: RES SMD 39.2K OHM 1% 1/16W 0402; Manufacturer 1: Vishay; Resistance: 39.2kR; Temperature Coefficient: 100ppm/°C; Power Rating: 63mW; Voltage Rating: 50V
R69 = RC0402FR-07100KL: RES SMD 100K OHM 1% 1/16W 0402; Manufacturer 1: Yageo; Power Rating: 63mW; Resistance: 100kR; Temperature Coefficient: 100ppm/°C; Voltage Rating: 50V
TP4 TP7 TP16 TP17 TP20 TP23 TP24 = TEST_POINT
U3 U15 = TLV62080DSG: IC REG BUCK ADJ 1.2A SYNC 8WSON; Manufacturer 1: Texas Instruments; Manufacturer Part Number 1: TLV62080DSGR; Quiescent Current: 30uA; Switching Frequency: 2MHz; Output Voltage: 4V; Number of Outputs: 1; Min Input Voltage: 2.5V; Max Input Voltage: 5.5V; Min Output Voltage: 500mV; Synchronous Rectifier: Yes; Output Type: Adjustable; Output Configuration: Positive
U8 = CMP-099-000001-1: IC OR CTRLR IDEAL DIODE SC70-6; Manufacturer 1: Texas Instruments
U10 = TLV70018DCK: IC REG LINEAR 1.8V 200MA SC70-5 Linear Voltage Regulator IC  1 Output  200mA SC-70-5; Manufacturer 1: Texas Instruments; Manufacturer Part Number 1: TLV70018DCKR; Max Power Dissipation: 320mW; Number of Outputs: 1; Dropout Voltage: 175mV; Max Input Voltage: 5.5V; Min Input Voltage: 2V; Min Current Limit: 220mA; Polarity: Positive; Output Voltage Accuracy: 2%; Quiescent Current: 30uA; Output Type: Fixed; Nominal Supply Current: 31uA
U14 = CMP-019-00053-2: Fixed Positive LDO Regulator, 2.8V, 0.23V Dropout, CMOS, PDSO4; Manufacturer 1: OnSemi; Max Supply Voltage: 5.5V; Dropout Voltage: 155mV; Min Supply Voltage: 1.7V; Output Current: 300mA

## Sheet MID_AR0234.SchDoc: =project_title
size Tabloid; PageSetup: Record=PageOptions¦CenterHorizontal=True¦CenterVertical=True¦PrintScale=0.71¦XCorrection=1.00¦YCorrection=1.00¦PrintKind=0¦BorderSize=5000000¦LeftOffset=0¦BottomOffset=0¦Orientation=2¦PaperLength=1000¦PaperWidth=1000¦Scale=100¦PaperSource=7¦PrintQuality=-4¦MediaType=1¦DitherType=10¦PrintScaleMode=1¦PaperKind=A4; CompanyName: Luxonis Holding; DrawnBy: Boris Chou / Blaz Kvas; Organization: Luxonis Holding; Address1: 1925 Harmony Park Drive; Address2: Westminster, CO; Address3: 80234; Address4: United States; DocumentNumber: D2088000; Revision: R1M1E1; SheetNumber: 5; SheetTotal: 11
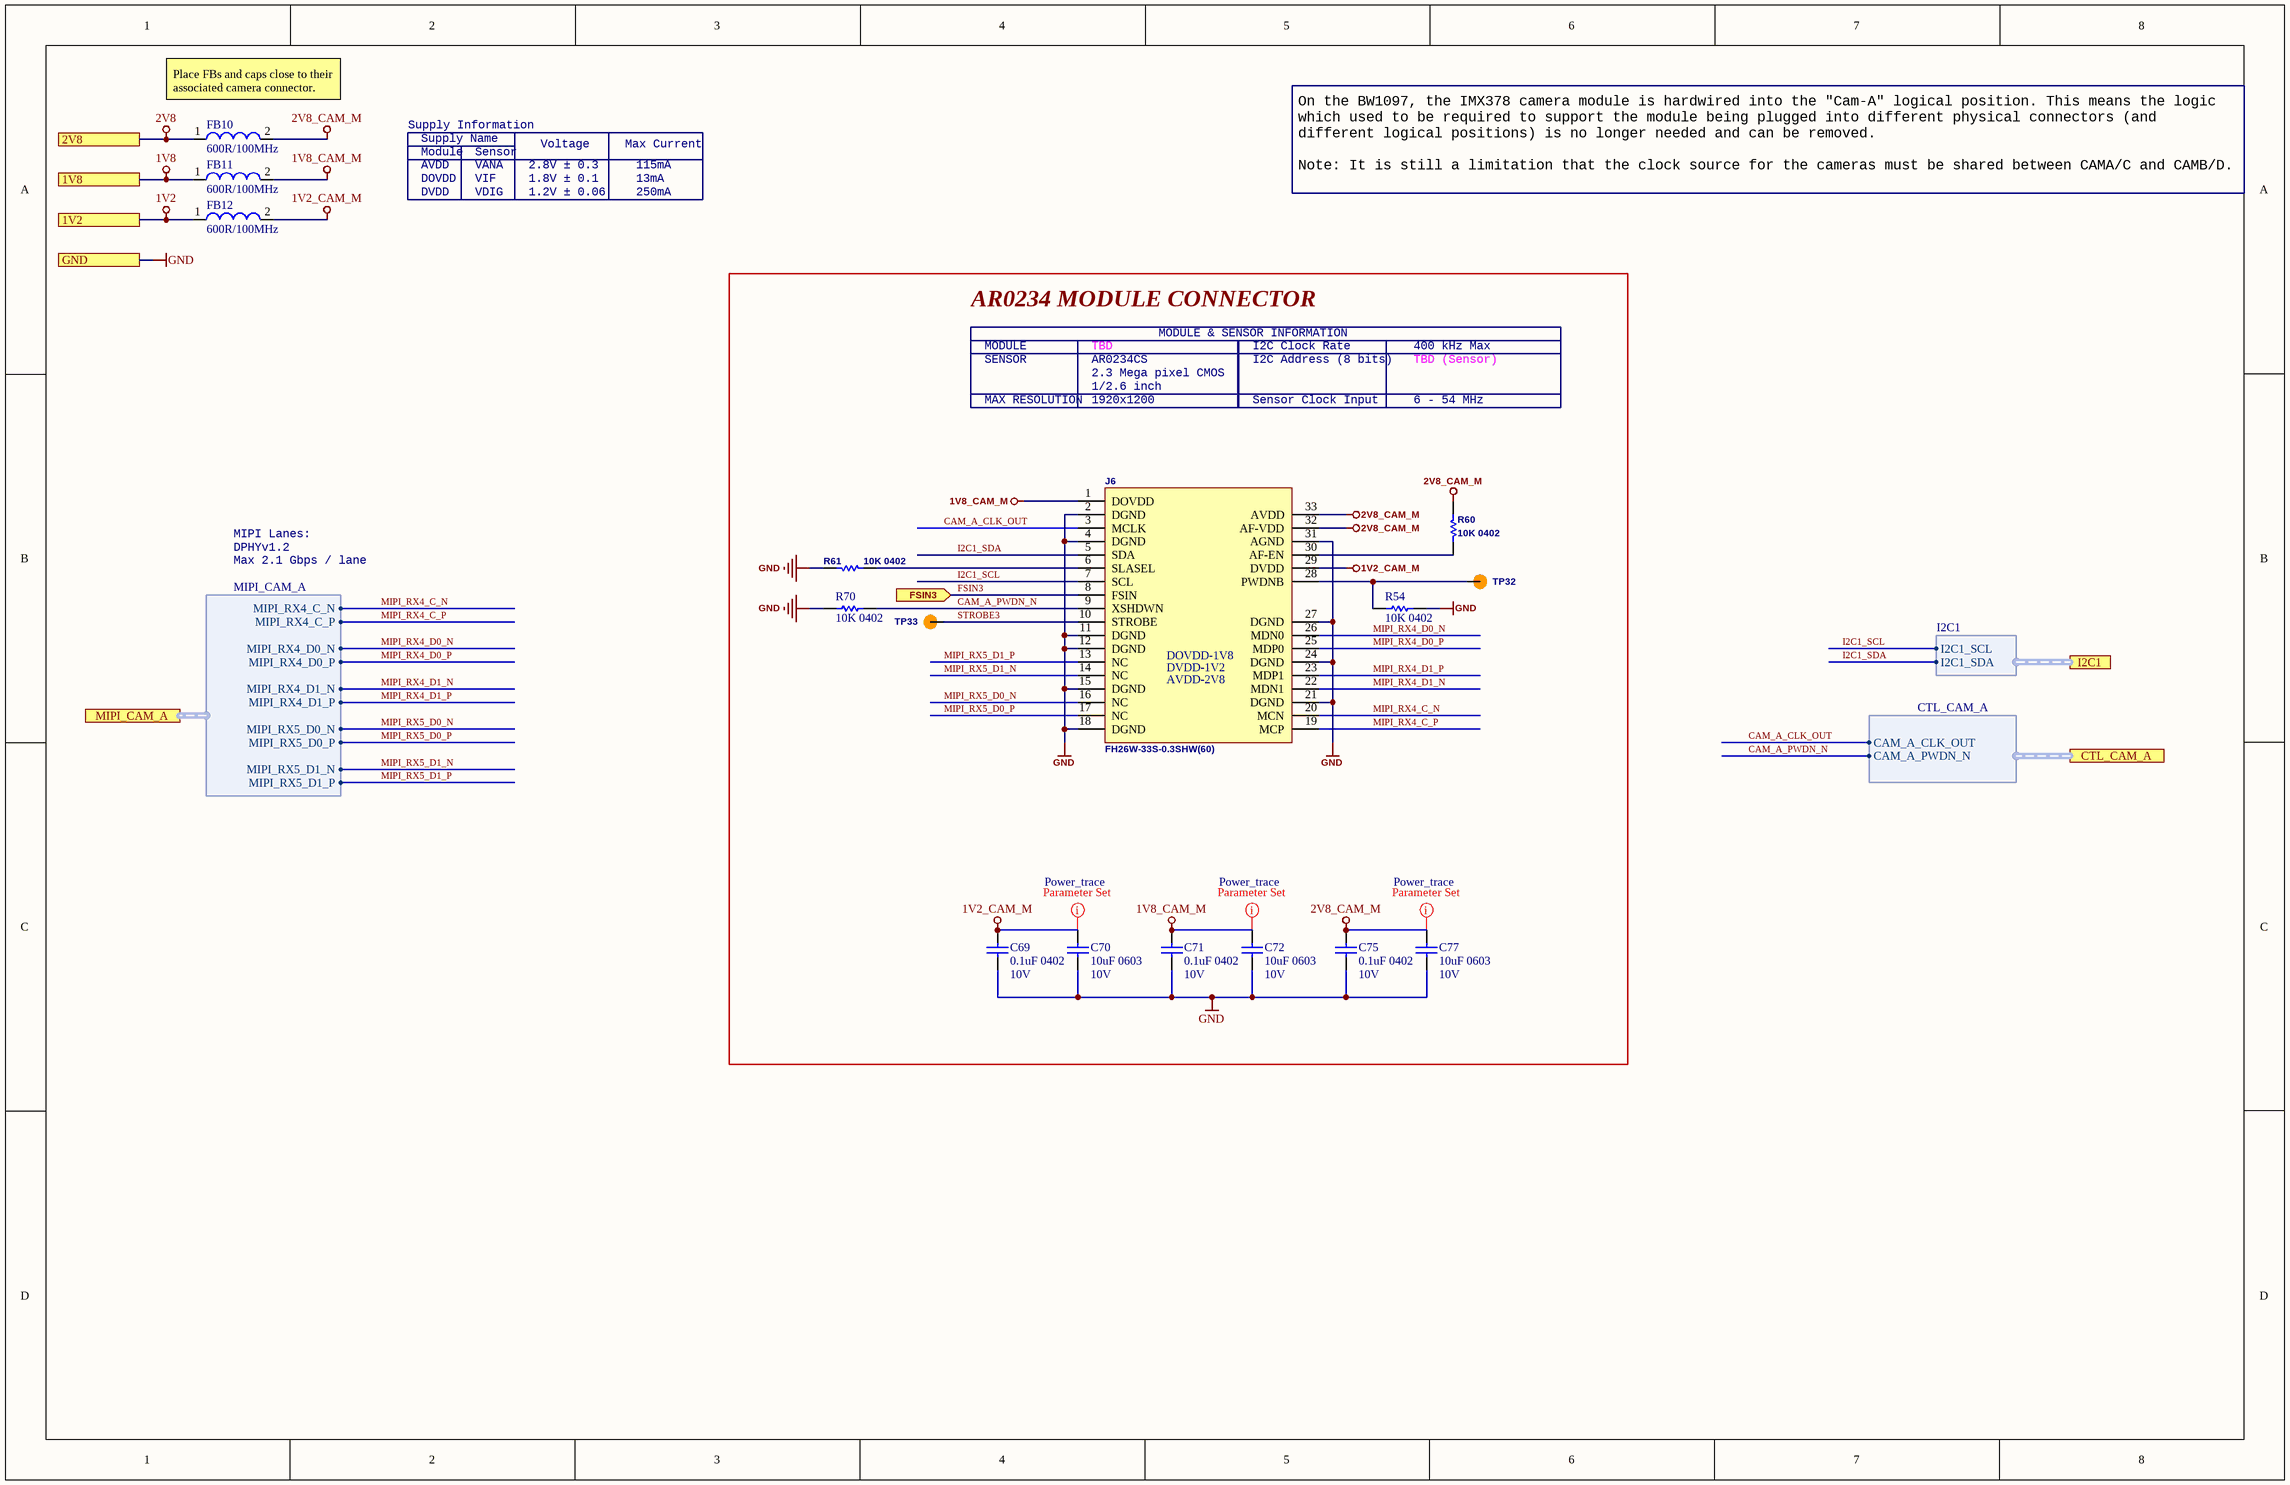
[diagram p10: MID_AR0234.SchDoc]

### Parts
C69  0.1uF 0402  Voltage Rating: 10V  [CAPC0402(1005)70_L]
C70  10uF 0603  Voltage Rating: 10V  [CAPC0603(1608)100_L]
C71  0.1uF 0402  Voltage Rating: 10V  [CAPC0402(1005)70_L]
C72  10uF 0603  Voltage Rating: 10V  [CAPC0603(1608)100_L]
C75  0.1uF 0402  Voltage Rating: 10V  [CAPC0402(1005)70_L]
C77  10uF 0603  Voltage Rating: 10V  [CAPC0603(1608)100_L]
FB10  600R/100MHz  [2508056017Y2]
FB11  600R/100MHz  [2508056017Y2]
FB12  600R/100MHz  [2508056017Y2]
J6  FH26W-33S-0.3SHW(60)  [AC-PY003-OV9282]
R54  10K 0402  [RESC0402(1005)_L]
R60  10K 0402  [RESC0402(1005)_L]
R61  10K 0402  [RESC0402(1005)_L]
R70  10K 0402  [RESC0402(1005)_L]
TP32  TP100_200_NS  [TP100_200_NS]  (value not drawn)  (no BOM)
TP33  TP100_200_NS  [TP100_200_NS]  (value not drawn)  (no BOM)

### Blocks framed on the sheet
AR0234 MODULE CONNECTOR: C69-C72 C75 C77 J6 R54 R60 R61 R70 TP32 TP33

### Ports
1V2, 1V8, 2V8, CTL_CAM_A (harness CTL_CAM_A), FSIN3 (in), GND, I2C1 (harness I2C1), MIPI_CAM_A (harness MIPI_CAM_A)

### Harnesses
I2C1: I2C1_SDA, I2C1_SCL
MIPI_CAM_A: MIPI_RX4_C_P, MIPI_RX4_C_N, MIPI_RX4_D0_P, MIPI_RX4_D0_N, MIPI_RX4_D1_P, MIPI_RX4_D1_N, MIPI_RX5_D0_P, MIPI_RX5_D0_N, MIPI_RX5_D1_P, MIPI_RX5_D1_N
CTL_CAM_A: CAM_A_PWDN_N, CAM_A_CLK_OUT

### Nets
1V2: FB12.1 ; port 1V2
1V2_CAM_M: C69.2 C70.2 FB12.2 J6.29(DVDD)
1V8: FB11.1 ; port 1V8
1V8_CAM_M: C71.2 C72.2 FB11.2 J6.1(DOVDD)
2V8: FB10.1 ; port 2V8
2V8_CAM_M: C75.2 C77.2 FB10.2 J6.32(AF-VDD) J6.33(AVDD) R60.1
GND: C69.1 C70.1 C71.1 C72.1 C75.1 C77.1 J6.2(DGND) J6.4(DGND) J6.11(DGND) J6.12(DGND) J6.15(DGND) J6.18(DGND) J6.21(DGND) J6.24(DGND) J6.27(DGND) J6.31(AGND) R54.2 R61.2 R70.1 ; port GND
CAM_A_CLK_OUT: J6.3(MCLK) ; port CTL_CAM_A.CAM_A_CLK_OUT
CAM_A_PWDN_N: J6.9(XSHDWN) R70.2 ; port CTL_CAM_A.CAM_A_PWDN_N
FSIN3: J6.8(FSIN) ; port FSIN3
I2C1_SCL: J6.7(SCL) ; port I2C1.I2C1_SCL
I2C1_SDA: J6.5(SDA) ; port I2C1.I2C1_SDA
MIPI_RX4_C_N: J6.20(MCN) ; port MIPI_CAM_A.MIPI_RX4_C_N
MIPI_RX4_C_P: J6.19(MCP) ; port MIPI_CAM_A.MIPI_RX4_C_P
MIPI_RX4_D0_N: J6.26(MDN0) ; port MIPI_CAM_A.MIPI_RX4_D0_N
MIPI_RX4_D0_P: J6.25(MDP0) ; port MIPI_CAM_A.MIPI_RX4_D0_P
MIPI_RX4_D1_N: J6.22(MDN1) ; port MIPI_CAM_A.MIPI_RX4_D1_N
MIPI_RX4_D1_P: J6.23(MDP1) ; port MIPI_CAM_A.MIPI_RX4_D1_P
MIPI_RX5_D0_N: J6.16(NC) ; port MIPI_CAM_A.MIPI_RX5_D0_N
MIPI_RX5_D0_P: J6.17(NC) ; port MIPI_CAM_A.MIPI_RX5_D0_P
MIPI_RX5_D1_N: J6.14(NC) ; port MIPI_CAM_A.MIPI_RX5_D1_N
MIPI_RX5_D1_P: J6.13(NC) ; port MIPI_CAM_A.MIPI_RX5_D1_P
STROBE3: J6.10(STROBE) TP33.1
NetJ6_6: J6.6(SLASEL) R61.1
NetJ6_28: J6.28(PWDNB) R54.1 TP32.1
NetJ6_30: J6.30(AF-EN) R60.2

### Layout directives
net class Power_trace: 1V2_CAM_M, 1V8_CAM_M, 2V8_CAM_M

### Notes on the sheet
- (near FB10) Place FBs and caps close to their associated camera connector.
- Supply Information
- AVDD
- Supply Name
- Module
- VANA
- Sensor
- 2.8V ± 0.3
- Voltage
- Max Current
- 115mA
- DOVDD
- DVDD
- VIF
- VDIG
- 1.8V ± 0.1
- 1.2V ± 0.06
- 13mA
- 250mA
- On the BW1097, the IMX378 camera module is hardwired into the "Cam-A" logical position. This means the logic which used to be required to support the module being plugged into different physical connectors (and different logical positions) is no longer needed and can be removed.
  Note: It is still a limitation that the clock source for the cameras must be shared between CAMA/C and CAMB/D.
- SENSOR
- MODULE
- AR0234CS
- TBD
- MODULE & SENSOR INFORMATION
- I2C Address (8 bits)
- I2C Clock Rate
- TBD (Sensor)
- 400 kHz Max
- MAX RESOLUTION
- 2.3 Mega pixel CMOS
- 1920x1200
- 1/2.6 inch
- Sensor Clock Input
- 6 - 54 MHz
- MIPI Lanes:
- Max 2.1 Gbps / lane
- DPHYv1.2

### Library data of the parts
C69 C71 C75 = GRM155R71A104JA01D: CAP CER 0.1UF 10V X7R 0402 5%; Manufacturer 1: Murata; Capacitance: 100nF
C70 C72 C77 = GRM188R61A106ME69D: as C14 on sheet POWER_GEN
FB10-FB12 = 2508056017Y2: FERRITE BEAD, 0.1OHM, 2A, 0805, 600R/100MHz; Manufacturer 1: Fair-Rite; Impedance: 600R; Tolerance: 25%; Resistance: 350mR; DC Resistance (DCR): 100mR; Test Frequency: 100MHz
J6 = AC_PY003-OV9282_CON: FFC/FPC Connector, 33 Contact(s), 1 Row(s), Female, Right Angle, Surface Mount Terminal; Manufacturer 1: Hirose
R54 R60 R61 R70 = RC0402FR-1310KL: RES SMD 10K OHM 1% 0402 1/16W Chip Resistor, 0402 [1005 Metric], 10 kohm, RC Series, 50 V, Thick Film, 62.5 mW; Manufacturer 1: Yageo; Resistance: 10kR; Temperature Coefficient: 100ppm/°C; Power Rating: 62.5mW; Voltage Rating: 50V
TP32 TP33 = TEST_POINT

## Sheet RIGHT_AR0234.SchDoc: =project_title
size Tabloid; CompanyName: Luxonis Holding; DrawnBy: Boris Chou / Blaz Kvas; Organization: Luxonis Holding; Address1: 1925 Harmony Park Drive; Address2: Westminster, CO; Address3: 80234; Address4: United States; DocumentNumber: D2088000; Revision: R1M1E1; SheetNumber: 10; SheetTotal: 11
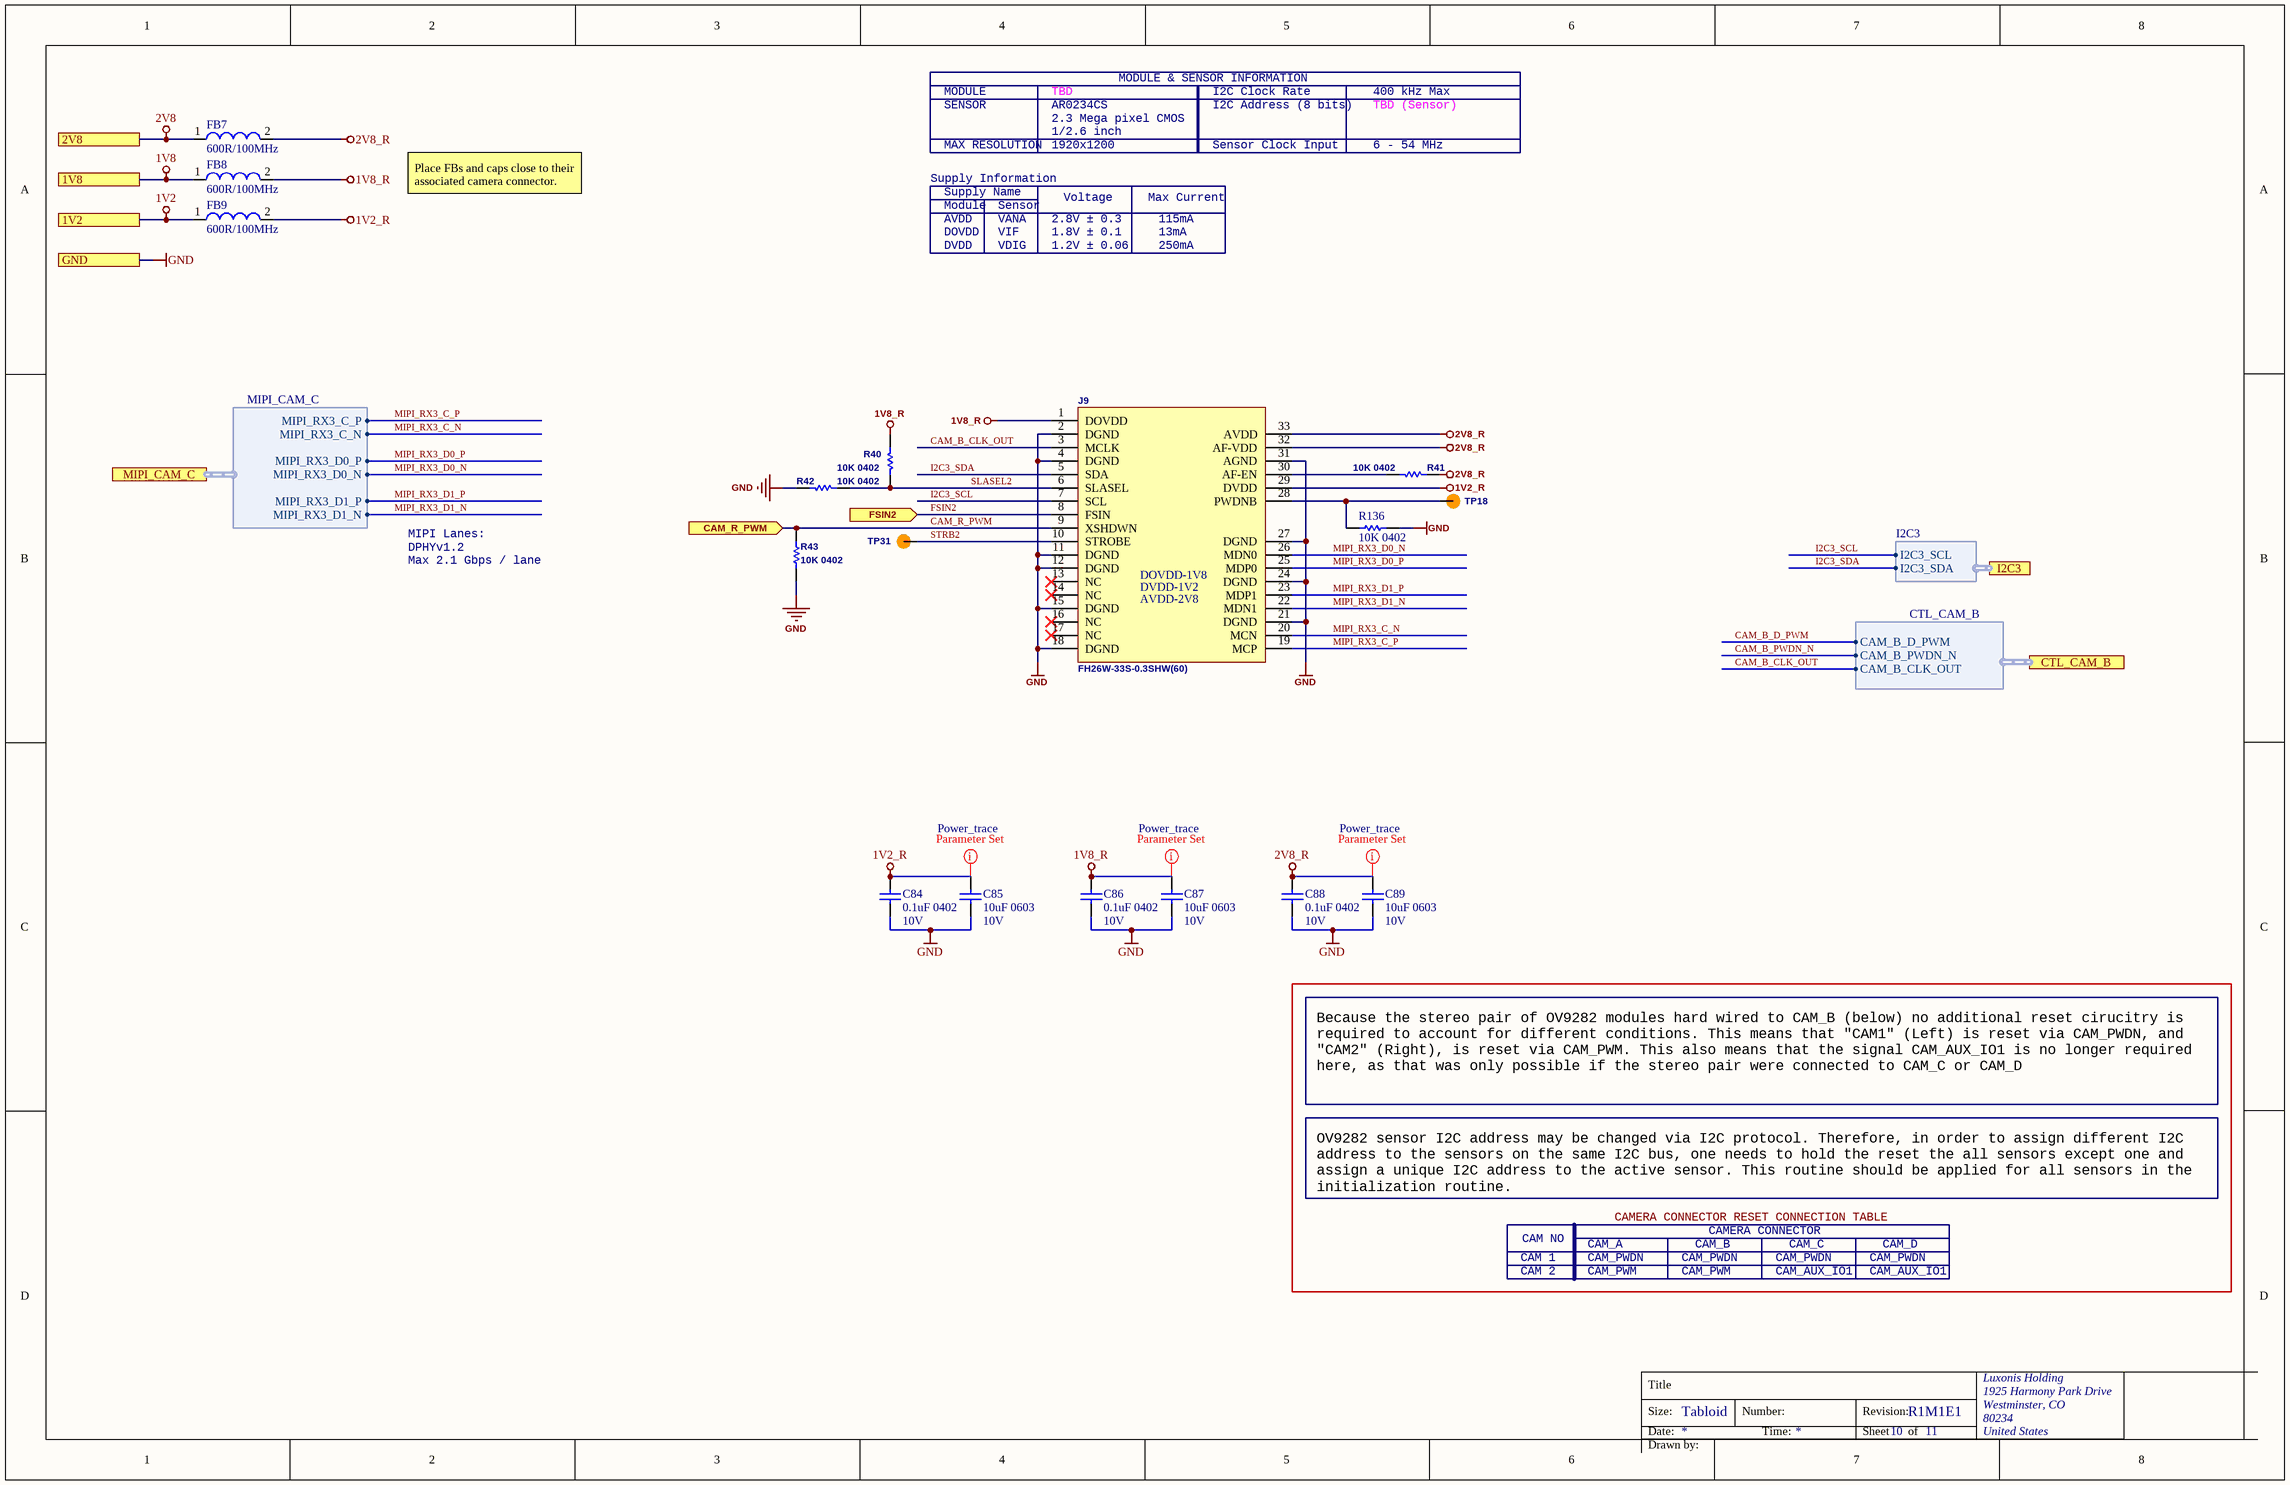
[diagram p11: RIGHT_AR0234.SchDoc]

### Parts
C84  0.1uF 0402  Voltage Rating: 10V  [CAPC0402(1005)70_L]
C85  10uF 0603  Voltage Rating: 10V  [CAPC0603(1608)100_L]
C86  0.1uF 0402  Voltage Rating: 10V  [CAPC0402(1005)70_L]
C87  10uF 0603  Voltage Rating: 10V  [CAPC0603(1608)100_L]
C88  0.1uF 0402  Voltage Rating: 10V  [CAPC0402(1005)70_L]
C89  10uF 0603  Voltage Rating: 10V  [CAPC0603(1608)100_L]
FB7  600R/100MHz  [2508056017Y2]
FB8  600R/100MHz  [2508056017Y2]
FB9  600R/100MHz  [2508056017Y2]
J9  FH26W-33S-0.3SHW(60)  [AC-PY003-OV9282]
R40  10K 0402  [RESC0402(1005)_L]
R41  10K 0402  [RESC0402(1005)_L]
R42  10K 0402  [RESC0402(1005)_L]
R43  10K 0402  [RESC0402(1005)_L]
R136  10K 0402  [RESC0402(1005)_L]
TP18  TP100_200_NS  [TP100_200_NS]  (value not drawn)  (no BOM)
TP31  TP100_200_NS  [TP100_200_NS]  (value not drawn)  (no BOM)

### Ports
1V2, 1V8, 2V8, CAM_R_PWM (in), CTL_CAM_B (harness CTL_CAM_B), FSIN2 (in), GND, I2C3 (harness I2C3), MIPI_CAM_C (harness MIPI_CAM_C)

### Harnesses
MIPI_CAM_C: MIPI_RX3_C_P, MIPI_RX3_C_N, MIPI_RX3_D0_P, MIPI_RX3_D0_N, MIPI_RX3_D1_P, MIPI_RX3_D1_N
I2C3: I2C3_SDA, I2C3_SCL
CTL_CAM_B: CAM_B_CLK_OUT, CAM_B_PWDN_N, CAM_B_D_PWM

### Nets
1V2: FB9.1 ; port 1V2
1V2_R: C84.2 C85.2 FB9.2 J9.29(DVDD)
1V8: FB8.1 ; port 1V8
1V8_R: C86.2 C87.2 FB8.2 J9.1(DOVDD) R40.1
2V8: FB7.1 ; port 2V8
2V8_R: C88.2 C89.2 FB7.2 J9.32(AF-VDD) J9.33(AVDD) R41.2
GND: C84.1 C85.1 C86.1 C87.1 C88.1 C89.1 J9.2(DGND) J9.4(DGND) J9.11(DGND) J9.12(DGND) J9.15(DGND) J9.18(DGND) J9.21(DGND) J9.24(DGND) J9.27(DGND) J9.31(AGND) R42.1 R43.1 R136.2 ; port GND
CAM_B_CLK_OUT: J9.3(MCLK) ; port CTL_CAM_B.CAM_B_CLK_OUT
CAM_R_PWM: J9.9(XSHDWN) R43.2 ; port CAM_R_PWM
FSIN2: J9.8(FSIN) ; port FSIN2
I2C3_SCL: J9.7(SCL) ; port I2C3.I2C3_SCL
I2C3_SDA: J9.5(SDA) ; port I2C3.I2C3_SDA
MIPI_RX3_C_N: J9.20(MCN) ; port MIPI_CAM_C.MIPI_RX3_C_N
MIPI_RX3_C_P: J9.19(MCP) ; port MIPI_CAM_C.MIPI_RX3_C_P
MIPI_RX3_D0_N: J9.26(MDN0) ; port MIPI_CAM_C.MIPI_RX3_D0_N
MIPI_RX3_D0_P: J9.25(MDP0) ; port MIPI_CAM_C.MIPI_RX3_D0_P
MIPI_RX3_D1_N: J9.22(MDN1) ; port MIPI_CAM_C.MIPI_RX3_D1_N
MIPI_RX3_D1_P: J9.23(MDP1) ; port MIPI_CAM_C.MIPI_RX3_D1_P
SLASEL2: J9.6(SLASEL) R40.2 R42.2
STRB2: J9.10(STROBE) TP31.1
NetJ9_28: J9.28(PWDNB) R136.1 TP18.1
NetJ9_30: J9.30(AF-EN) R41.1

Not connected (* = marked no-connect by the designer): J9 13(NC)* 14(NC)* 16(NC)* 17(NC)*

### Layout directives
net class Power_trace: 1V2_R, 1V8_R, 2V8_R

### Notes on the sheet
- MODULE
- TBD
- MODULE & SENSOR INFORMATION
- I2C Clock Rate
- 400 kHz Max
- SENSOR
- MAX RESOLUTION
- 2.3 Mega pixel CMOS
- 1920x1200
- AR0234CS
- 1/2.6 inch
- I2C Address (8 bits)
- Sensor Clock Input
- TBD (Sensor)
- 6 - 54 MHz
- Place FBs and caps close to their associated camera connector.
- Supply Information
- AVDD
- Supply Name
- Module
- VANA
- Sensor
- 2.8V ± 0.3
- Voltage
- Max Current
- 115mA
- DOVDD
- DVDD
- VIF
- VDIG
- 1.8V ± 0.1
- 1.2V ± 0.06
- 13mA
- 250mA
- MIPI Lanes:
- Max 2.1 Gbps / lane
- DPHYv1.2
- Because the stereo pair of OV9282 modules hard wired to CAM_B (below) no additional reset cirucitry is required to account for different conditions. This means that "CAM1" (Left) is reset via CAM_PWDN, and "CAM2" (Right), is reset via CAM_PWM. This also means that the signal CAM_AUX_IO1 is no longer required here, as that was only possible if the stereo pair were connected to CAM_C or CAM_D
- OV9282 sensor I2C address may be changed via I2C protocol. Therefore, in order to assign different I2C address to the sensors on the same I2C bus, one needs to hold the reset the all sensors except one and assign a unique I2C address to the active sensor. This routine should be applied for all sensors in the initialization routine.
- CAMERA CONNECTOR RESET CONNECTION TABLE
- CAMERA CONNECTOR
- CAM 1
- CAM 2
- CAM NO
- CAM_A
- CAM_PWDN
- CAM_PWM
- CAM_B
- CAM_AUX_IO1
- CAM_C
- CAM_D

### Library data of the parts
C84 C86 C88 = GRM155R71A104JA01D: as C69 on sheet MID_AR0234
C85 C87 C89 = GRM188R61A106ME69D: as C14 on sheet POWER_GEN
FB7-FB9 = 2508056017Y2: as FB10 on sheet MID_AR0234
J9 = AC_PY003-OV9282_CON: as J6 on sheet MID_AR0234
R40-R43 R136 = RC0402FR-1310KL: as R54 on sheet MID_AR0234
TP18 TP31 = TEST_POINT

## Sheet LEFT_AR0234.SchDoc: =project_title
size Tabloid; PageSetup: Record=PageOptions¦CenterHorizontal=True¦CenterVertical=True¦PrintScale=0.71¦XCorrection=1.00¦YCorrection=1.00¦PrintKind=0¦BorderSize=5000000¦LeftOffset=0¦BottomOffset=0¦Orientation=2¦PaperLength=1000¦PaperWidth=1000¦Scale=100¦PaperSource=7¦PrintQuality=-4¦MediaType=1¦DitherType=10¦PrintScaleMode=1¦PaperKind=A4; CompanyName: Luxonis Holding; DrawnBy: Boris Chou / Blaz Kvas; Organization: Luxonis Holding; Address1: 1925 Harmony Park Drive; Address2: Westminster, CO; Address3: 80234; Address4: United States; DocumentNumber: D2088000; Revision: R1M1E1; SheetNumber: 6; SheetTotal: 11
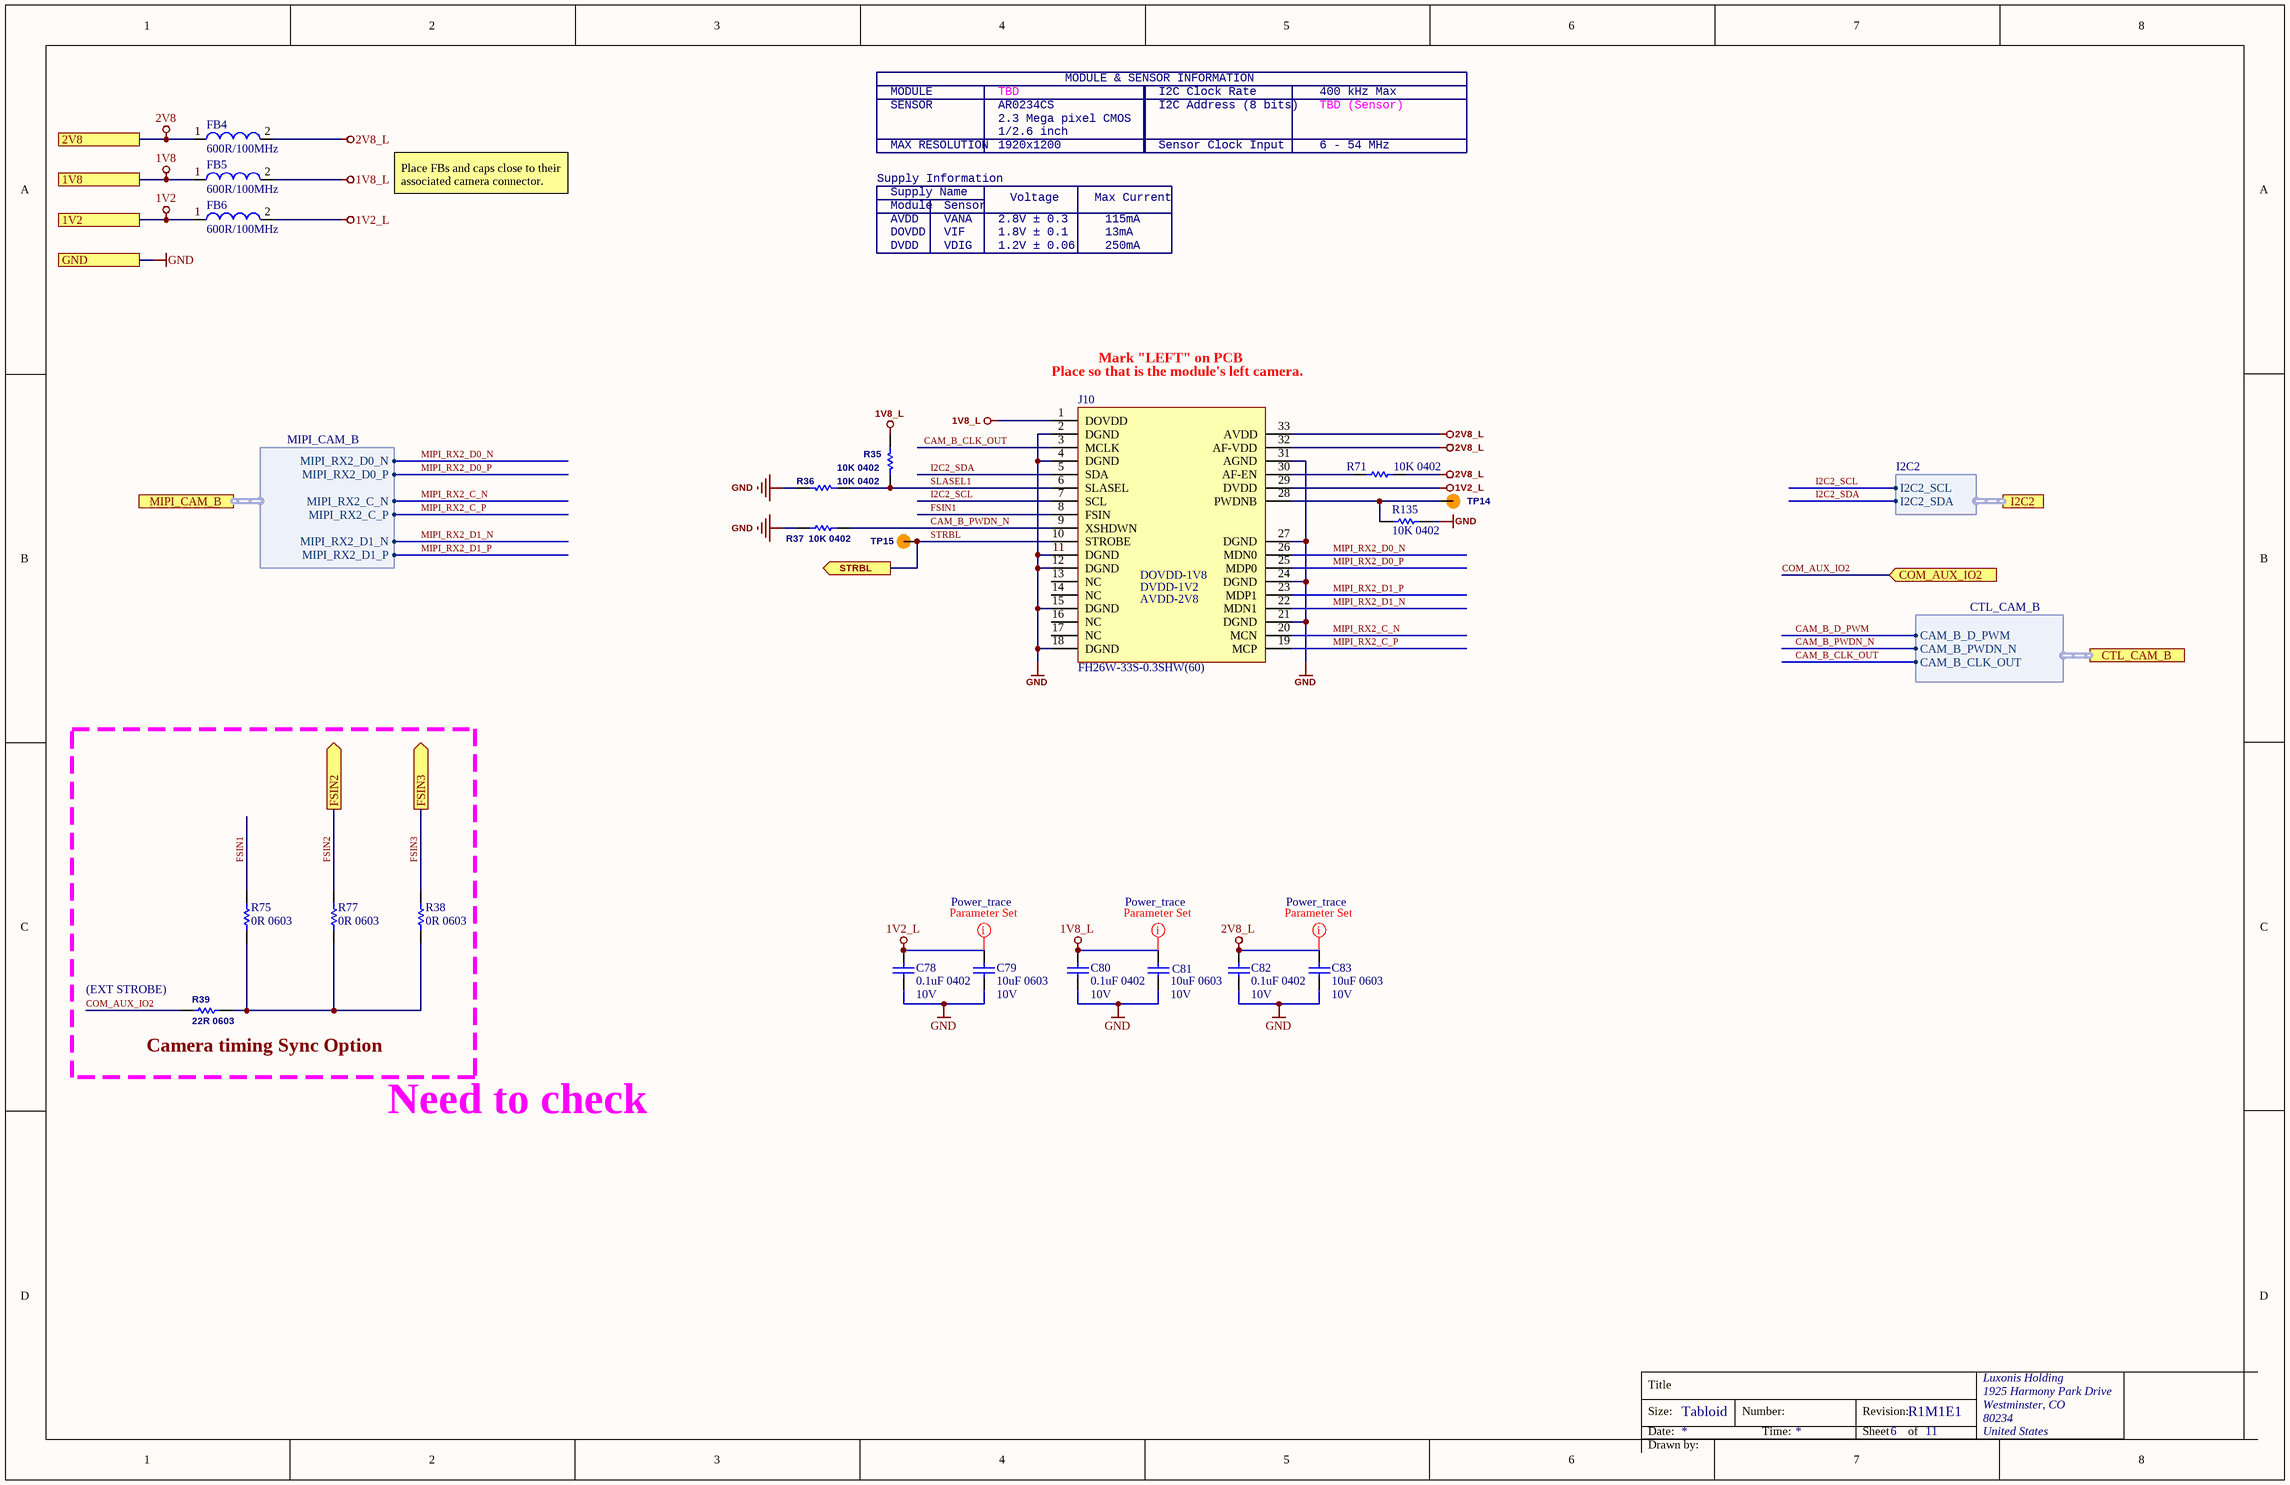
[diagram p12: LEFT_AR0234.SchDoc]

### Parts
C78  0.1uF 0402  Voltage Rating: 10V  [CAPC0402(1005)70_L]
C79  10uF 0603  Voltage Rating: 10V  [CAPC0603(1608)100_L]
C80  0.1uF 0402  Voltage Rating: 10V  [CAPC0402(1005)70_L]
C81  10uF 0603  Voltage Rating: 10V  [CAPC0603(1608)100_L]
C82  0.1uF 0402  Voltage Rating: 10V  [CAPC0402(1005)70_L]
C83  10uF 0603  Voltage Rating: 10V  [CAPC0603(1608)100_L]
FB4  600R/100MHz  [2508056017Y2]
FB5  600R/100MHz  [2508056017Y2]
FB6  600R/100MHz  [2508056017Y2]
J10  FH26W-33S-0.3SHW(60)  [AC-PY003-OV9282]
R35  10K 0402  [RESC0402(1005)_L]
R36  10K 0402  [RESC0402(1005)_L]
R37  10K 0402  [RESC0402(1005)_L]
R38  0R 0603  [RESC0603(1608)_L]
R39  22R 0603  [RESC0603(1608)_L]
R71  10K 0402  [RESC0402(1005)_L]
R75  0R 0603  [RESC0603(1608)_L]
R77  0R 0603  [RESC0603(1608)_L]
R135  10K 0402  [RESC0402(1005)_L]
TP14  TP100_200_NS  [TP100_200_NS]  (value not drawn)  (no BOM)
TP15  TP100_200_NS  [TP100_200_NS]  (value not drawn)  (no BOM)

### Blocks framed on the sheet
Camera timing Sync Option: R38 R39 R75 R77

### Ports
1V2, 1V8, 2V8, COM_AUX_IO2 (in), CTL_CAM_B (harness CTL_CAM_B), FSIN2 (out), FSIN3 (out), GND, I2C2 (harness I2C2), MIPI_CAM_B (harness MIPI_CAM_B), STRBL (out)

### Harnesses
I2C2: I2C2_SDA, I2C2_SCL
MIPI_CAM_B: MIPI_RX2_D1_P, MIPI_RX2_D1_N, MIPI_RX2_D0_N, MIPI_RX2_D0_P, MIPI_RX2_C_N, MIPI_RX2_C_P
CTL_CAM_B: CAM_B_CLK_OUT, CAM_B_PWDN_N, CAM_B_D_PWM

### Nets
1V2: FB6.1 ; port 1V2
1V2_L: C78.2 C79.2 FB6.2 J10.29(DVDD)
1V8: FB5.1 ; port 1V8
1V8_L: C80.2 C81.2 FB5.2 J10.1(DOVDD) R35.1
2V8: FB4.1 ; port 2V8
2V8_L: C82.2 C83.2 FB4.2 J10.32(AF-VDD) J10.33(AVDD) R71.2
GND: C78.1 C79.1 C80.1 C81.1 C82.1 C83.1 J10.2(DGND) J10.4(DGND) J10.11(DGND) J10.12(DGND) J10.15(DGND) J10.18(DGND) J10.21(DGND) J10.24(DGND) J10.27(DGND) J10.31(AGND) R36.1 R37.2 R135.2 ; port GND
CAM_B_CLK_OUT: J10.3(MCLK) ; port CTL_CAM_B.CAM_B_CLK_OUT
CAM_B_PWDN_N: J10.9(XSHDWN) R37.1 ; port CTL_CAM_B.CAM_B_PWDN_N
COM_AUX_IO2: R39.2 ; port COM_AUX_IO2
FSIN1: J10.8(FSIN) R75.2
FSIN2: R77.2 ; port FSIN2
FSIN3: R38.2 ; port FSIN3
I2C2_SCL: J10.7(SCL) ; port I2C2.I2C2_SCL
I2C2_SDA: J10.5(SDA) ; port I2C2.I2C2_SDA
MIPI_RX2_C_N: J10.20(MCN) ; port MIPI_CAM_B.MIPI_RX2_C_N
MIPI_RX2_C_P: J10.19(MCP) ; port MIPI_CAM_B.MIPI_RX2_C_P
MIPI_RX2_D0_N: J10.26(MDN0) ; port MIPI_CAM_B.MIPI_RX2_D0_N
MIPI_RX2_D0_P: J10.25(MDP0) ; port MIPI_CAM_B.MIPI_RX2_D0_P
MIPI_RX2_D1_N: J10.22(MDN1) ; port MIPI_CAM_B.MIPI_RX2_D1_N
MIPI_RX2_D1_P: J10.23(MDP1) ; port MIPI_CAM_B.MIPI_RX2_D1_P
SLASEL1: J10.6(SLASEL) R35.2 R36.2
STRBL: J10.10(STROBE) TP15.1 ; port STRBL
NetJ10_28: J10.28(PWDNB) R135.1 TP14.1
NetJ10_30: J10.30(AF-EN) R71.1
NetR38_1: R38.1 R39.1 R75.1 R77.1

Not connected (* = marked no-connect by the designer): J10 13(NC) 14(NC) 16(NC) 17(NC)

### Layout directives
net class Power_trace: 1V2_L, 1V8_L, 2V8_L

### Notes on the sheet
- MODULE
- TBD
- MODULE & SENSOR INFORMATION
- I2C Clock Rate
- 400 kHz Max
- SENSOR
- MAX RESOLUTION
- 2.3 Mega pixel CMOS
- 1920x1200
- AR0234CS
- 1/2.6 inch
- I2C Address (8 bits)
- Sensor Clock Input
- TBD (Sensor)
- 6 - 54 MHz
- Place FBs and caps close to their associated camera connector.
- Supply Information
- AVDD
- Supply Name
- Module
- VANA
- Sensor
- 2.8V ± 0.3
- Voltage
- Max Current
- 115mA
- DOVDD
- DVDD
- VIF
- VDIG
- 1.8V ± 0.1
- 1.2V ± 0.06
- 13mA
- 250mA
- Mark "LEFT" on PCB
- (near J10) Place so that is the module's left camera.
- (near R39) (EXT STROBE)
- Need to check

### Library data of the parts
C78 C80 C82 = GRM155R71A104JA01D: as C69 on sheet MID_AR0234
C79 C81 C83 = GRM188R61A106ME69D: as C14 on sheet POWER_GEN
FB4-FB6 = 2508056017Y2: as FB10 on sheet MID_AR0234
J10 = AC_PY003-OV9282_CON: as J6 on sheet MID_AR0234
R35-R37 R71 R135 = RC0402FR-1310KL: as R54 on sheet MID_AR0234
R38 R75 R77 = CRCW06030000Z0EA: as R17 on sheet PoE_Si3404
R39 = RC0603FR-0722RL: RES SMD 22 OHM 1% 1/10W 0603; Manufacturer 1: Yageo; Temperature Coefficient: 100ppm/°C; Power Rating: 100mW; Voltage Rating: 50V
TP14 TP15 = TEST_POINT

## Sheet IMU.SchDoc: =project_title
size Tabloid; CompanyName: Luxonis Holding; DrawnBy: Boris Chou / Blaz Kvas; Organization: Luxonis Holding; Address1: 1925 Harmony Park Drive; Address2: Westminster, CO; Address3: 80234; Address4: United States; DocumentNumber: D2088000; Revision: R1M1E1; SheetNumber: 4; SheetTotal: 11
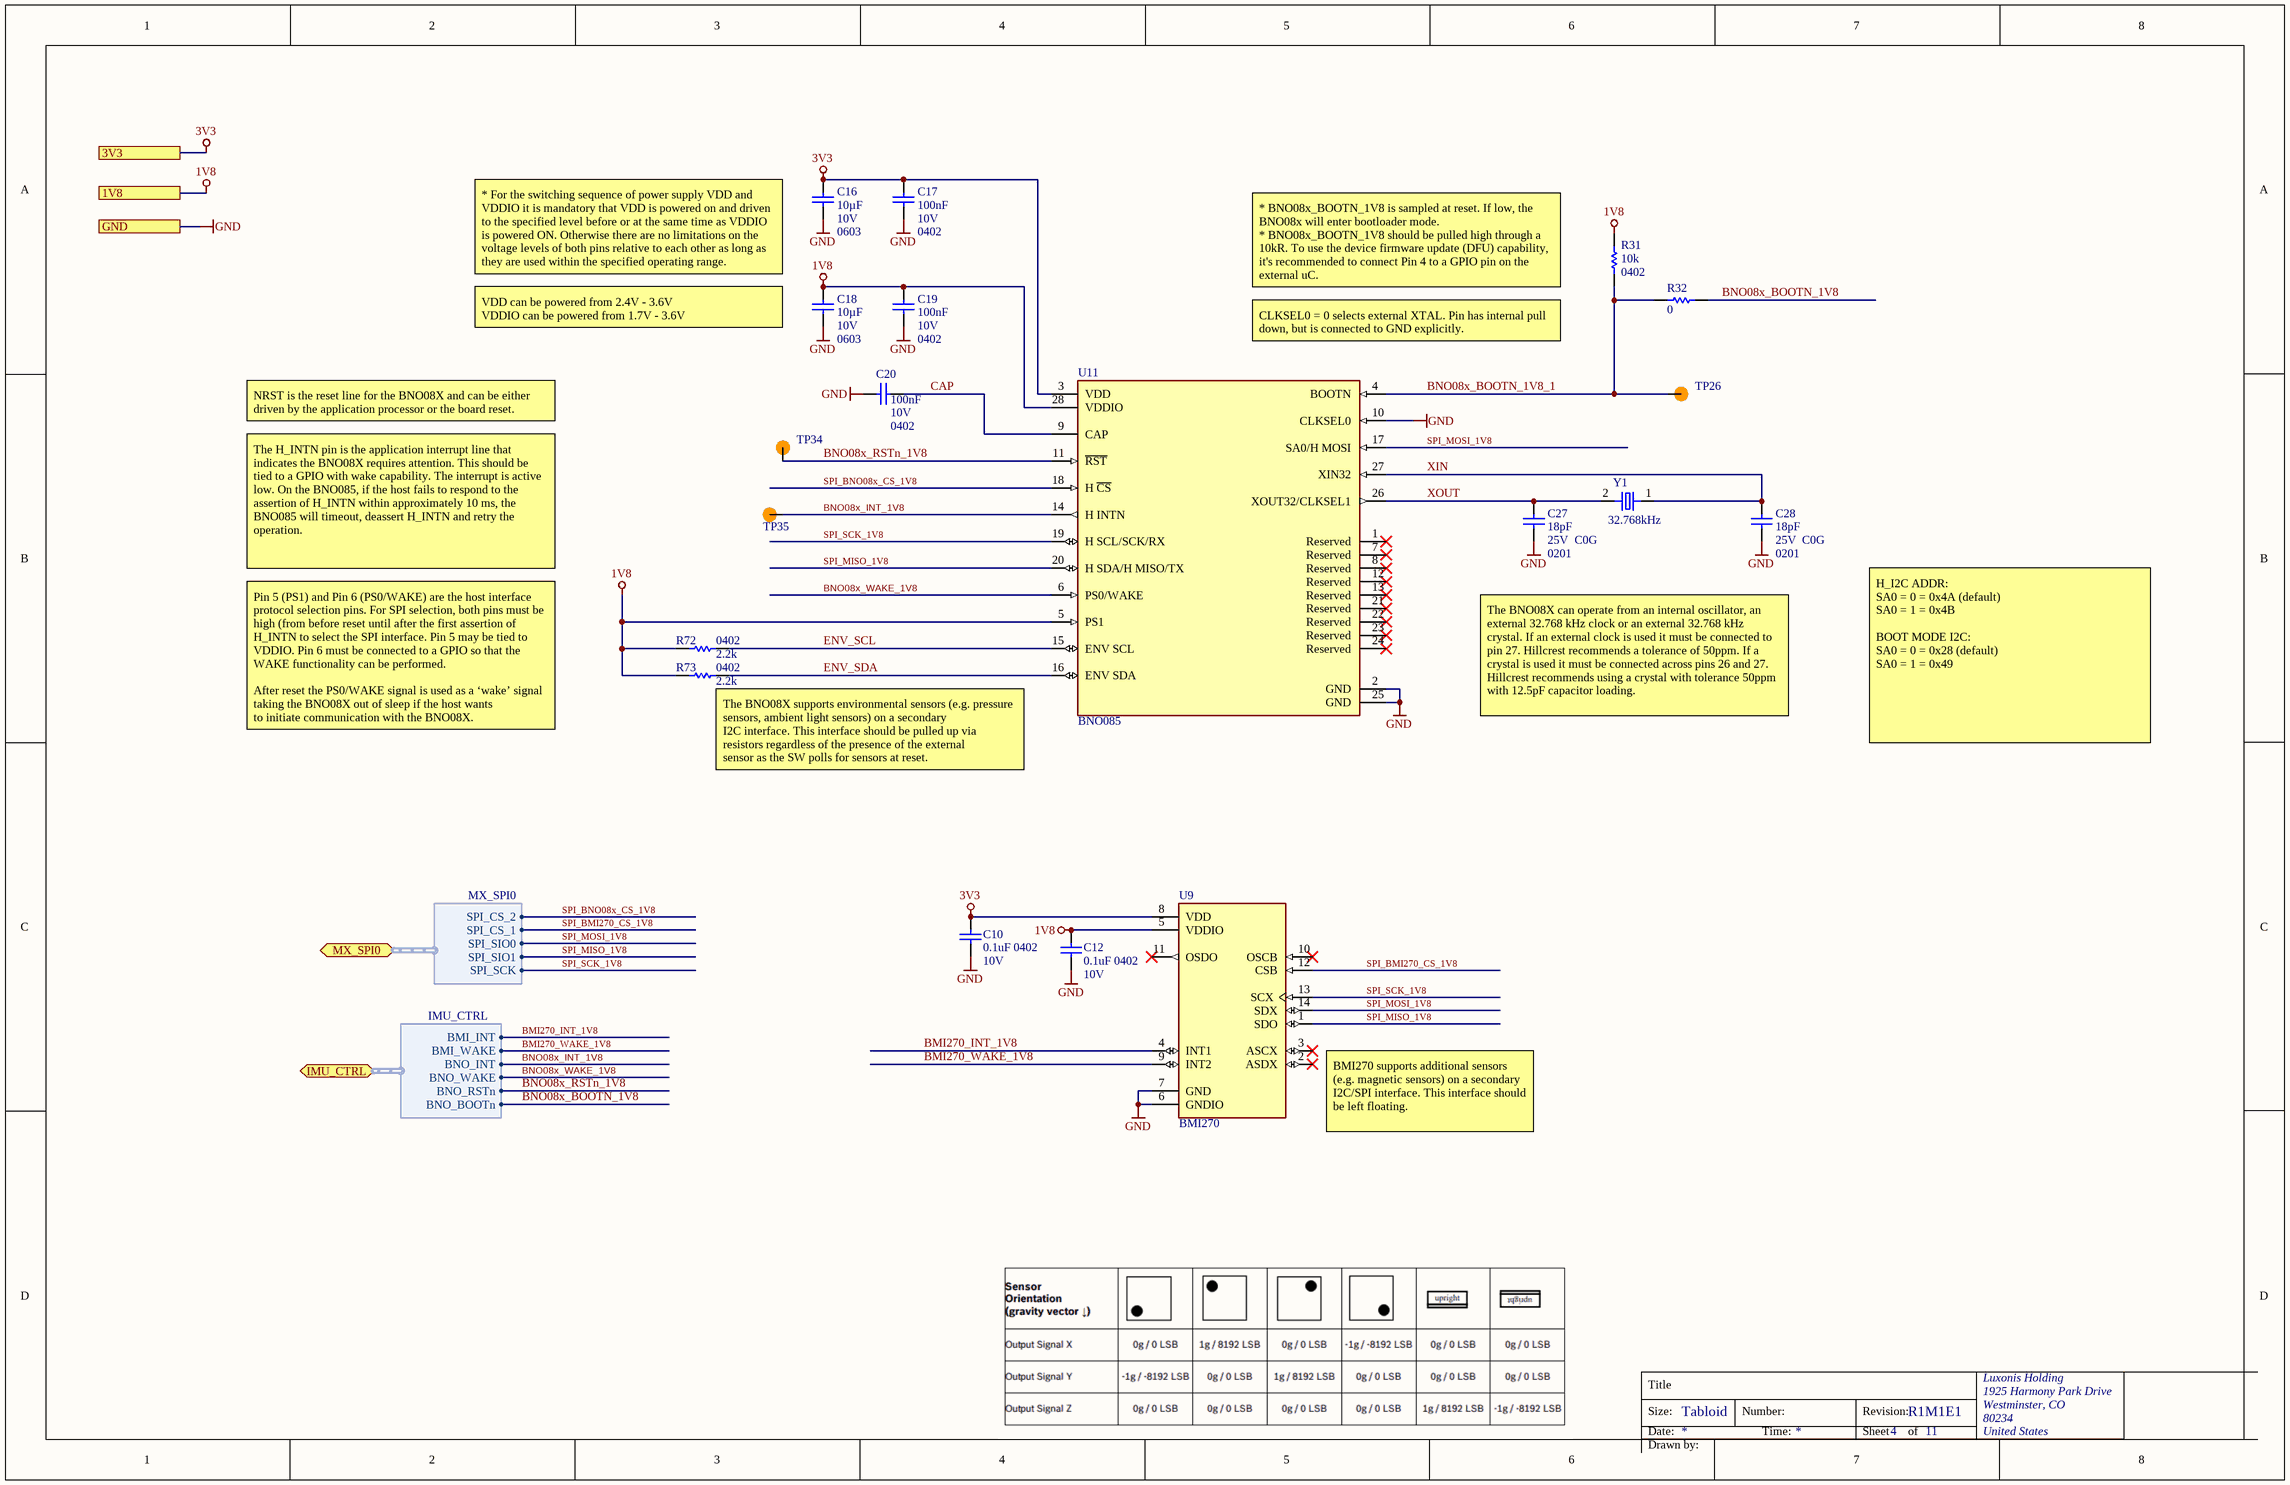
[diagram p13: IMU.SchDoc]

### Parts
C10  0.1uF 0402  Voltage Rating: 10V  [CAPC0402(1005)70_L]
C12  0.1uF 0402  Voltage Rating: 10V  [CAPC0402(1005)70_L]
C16  value 10µF  Case/Package: 0603  Voltage Rating: 10V  [CAPC0603(1608)100_L]  (hidden comment: GRM188R61A106ME69D)
C17  value 100nF  Case/Package: 0402  Voltage Rating: 10V  [CAPC0402(1005)70_N]  (hidden comment: GRM155R71A104JA01D)
C18  value 10µF  Case/Package: 0603  Voltage Rating: 10V  [CAPC0603(1608)100_L]  (hidden comment: GRM188R61A106ME69D)
C19  value 100nF  Case/Package: 0402  Voltage Rating: 10V  [CAPC0402(1005)70_N]  (hidden comment: GRM155R71A104JA01D)
C20  value 100nF  Case/Package: 0402  Voltage Rating: 10V  [CAPC0402(1005)70_N]  (hidden comment: GRM155R71A104JA01D)
C27  value 18pF  Case/Package: 0201  Voltage Rating: 25V  Dielectric: C0G  [CAPC0201(0603)33_L]  (hidden comment: GRM0335C1E180FA01D)
C28  value 18pF  Case/Package: 0201  Voltage Rating: 25V  Dielectric: C0G  [CAPC0201(0603)33_L]  (hidden comment: GRM0335C1E180FA01D)
R31  value 10k  Case/Package: 0402  [RESC0402(1005)_L]  (hidden comment: RC0402FR-1310KL)
R32  value 0  [RESC0402(1005)_L]  (hidden comment: Default resistor symbol)
R72  value 2.2k  Case/Package: 0402  [RESC0402(1005)_L]  (hidden comment: RC0402FR-072K2L)
R73  value 2.2k  Case/Package: 0402  [RESC0402(1005)_L]  (hidden comment: RC0402FR-072K2L)
TP26  TEST_POINT  [TP100_200_NS]  (value not drawn)  (no BOM)
TP34  TEST_POINT  [TP100_200_NS]  (value not drawn)  (no BOM)
TP35  TEST_POINT  [TP100_200_NS]  (value not drawn)  (no BOM)
U9  BMI270  [XDCR_BMI270]
U11  BNO085  [BNO085]
Y1  Frequency: 32.768kHz  [ABS06-127-32.768KHZ-T]  (hidden comment: ABS06-127-32.768KHZ-T)

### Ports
1V8, 3V3, GND, IMU_CTRL (bidir, harness IMU_CTRL), MX_SPI0 (bidir, harness MX_SPI0)

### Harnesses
MX_SPI0: SPI_SIO0, SPI_SIO1, SPI_CS_1, SPI_SCK, SPI_CS_2
IMU_CTRL: BMI_INT, BMI_WAKE, BNO_INT, BNO_WAKE, BNO_RSTn, BNO_BOOTn

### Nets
1V8: C12.2 C18.2 C19.2 R31.2 R72.1 R73.1 U9.5(VDDIO) U11.5(PS1) U11.28(VDDIO) ; port 1V8
3V3: C10.2 C16.2 C17.2 U9.8(VDD) U11.3(VDD) ; port 3V3
GND: C10.1 C12.1 C16.1 C17.1 C18.1 C19.1 C20.2 C27.1 C28.1 U9.6(GNDIO) U9.7(GND) U11.2(GND) U11.10(CLKSEL0) U11.25(GND) ; port GND
BMI270_INT_1V8: U9.4(INT1) ; port IMU_CTRL.BMI_INT
BMI270_WAKE_1V8: U9.9(INT2) ; port IMU_CTRL.BMI_WAKE
BNO08x_BOOTN_1V8: R32.2 ; port IMU_CTRL.BNO_BOOTn
BNO08x_BOOTN_1V8_1: R31.1 R32.1 TP26.1 U11.4(BOOTN)
BNO08x_INT_1V8: TP35.1 U11.14(H_INTN) ; port IMU_CTRL.BNO_INT  [project net BNO085_INT_1V8]
BNO08x_RSTn_1V8: TP34.1 U11.11(~{RST}) ; port IMU_CTRL.BNO_RSTn
BNO08x_WAKE_1V8: U11.6(PS0/WAKE) ; port IMU_CTRL.BNO_WAKE  [project net BNO085_WAKE_1V8]
CAP: C20.1 U11.9(CAP)
ENV_SCL: R72.2 U11.15(ENV_SCL)
ENV_SDA: R73.2 U11.16(ENV_SDA)
SPI_BMI270_CS_1V8: U9.12(CSB) ; port MX_SPI0.SPI_CS_1
SPI_BNO08x_CS_1V8: U11.18(H_~{CS}) ; port MX_SPI0.SPI_CS_2  [project net SPI_BNO085_CS_1V8]
SPI_MISO_1V8: U9.1(SDO) U11.20(H_SDA/H_MISO/TX) ; port MX_SPI0.SPI_SIO1
SPI_MOSI_1V8: U9.14(SDX) U11.17(SA0/H_MOSI) ; port MX_SPI0.SPI_SIO0
SPI_SCK_1V8: U9.13(SCX) U11.19(H_SCL/SCK/RX) ; port MX_SPI0.SPI_SCK
XIN: C28.2 U11.27(XIN32) Y1.1
XOUT: C27.2 U11.26(XOUT32/CLKSEL1) Y1.2

Not connected (* = marked no-connect by the designer): U9 2(ASDX)* 3(ASCX)* 10(OSCB)* 11(OSDO)*; U11 1(Reserved)* 7(Reserved)* 8(Reserved)* 12(Reserved)* 13(Reserved)* 21(Reserved)* 22(Reserved)* 23(Reserved)* 24(Reserved)*

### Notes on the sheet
- * For the switching sequence of power supply VDD and VDDIO it is mandatory that VDD is powered on and driven to the specified level before or at the same time as VDDIO is powered ON. Otherwise there are no limitations on the voltage levels of both pins relative to each other as long as they are used within the specified operating range.
- * BNO08x_BOOTN_1V8 is sampled at reset. If low, the BNO08x will enter bootloader mode.
  * BNO08x_BOOTN_1V8 should be pulled high through a 10kR. To use the device firmware update (DFU) capability, it's recommended to connect Pin 4 to a GPIO pin on the external uC.
- (near C18) VDD can be powered from 2.4V - 3.6V
  VDDIO can be powered from 1.7V - 3.6V
- CLKSEL0 = 0 selects external XTAL. Pin has internal pull down, but is connected to GND explicitly.
- NRST is the reset line for the BNO08X and can be either driven by the application processor or the board reset.
- The H_INTN pin is the application interrupt line that indicates the BNO08X requires attention. This should be tied to a GPIO with wake capability. The interrupt is active low. On the BNO085, if the host fails to respond to the assertion of H_INTN within approximately 10 ms, the BNO085 will timeout, deassert H_INTN and retry the operation.
- Pin 5 (PS1) and Pin 6 (PS0/WAKE) are the host interface protocol selection pins. For SPI selection, both pins must be high (from before reset until after the first assertion of H_INTN to select the SPI interface. Pin 5 may be tied to VDDIO. Pin 6 must be connected to a GPIO so that the WAKE functionality can be performed.
  After reset the PS0/WAKE signal is used as a ‘wake’ signal taking the BNO08X out of sleep if the host wants
  to initiate communication with the BNO08X.
- (near R73) The BNO08X supports environmental sensors (e.g. pressure sensors, ambient light sensors) on a secondary
  I2C interface. This interface should be pulled up via resistors regardless of the presence of the external
  sensor as the SW polls for sensors at reset.
- The BNO08X can operate from an internal oscillator, an external 32.768 kHz clock or an external 32.768 kHz crystal. If an external clock is used it must be connected to pin 27. Hillcrest recommends a tolerance of 50ppm. If a crystal is used it must be connected across pins 26 and 27. Hillcrest recommends using a crystal with tolerance 50ppm with 12.5pF capacitor loading.
- H_I2C ADDR:
  SA0 = 0 = 0x4A (default)
  SA0 = 1 = 0x4B
  BOOT MODE I2C:
  SA0 = 0 = 0x28 (default)
  SA0 = 1 = 0x49
- (near U9) BMI270 supports additional sensors (e.g. magnetic sensors) on a secondary I2C/SPI interface. This interface should be left floating.

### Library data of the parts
C10 C12 = GRM155R71A104JA01D: as C69 on sheet MID_AR0234
C16 C18 = CMP-004-000018-2: CAP CER 10UF 10V X5R 0603 20%; Manufacturer 1: Murata
C17 C19 C20 = CMP-108-000015-2: CAP CER 0.1UF 10V X7R 0402 5%; Manufacturer 1: Murata
C27 C28 = CMP-004-000003-2: Cap Ceramic 18pF 25V C0G 1% Pad SMD 0201 125C T/R; Manufacturer 1: Murata
R31 = CMP-115-000004-6: RES SMD 10K OHM 1% 0402 1/16W Chip Resistor, 0402 [1005 Metric], 10 kohm, RC Series, 50 V, Thick Film, 62.5 mW; Manufacturer 1: Yageo; Temperature Coefficient: 100ppm/°C; Power Rating: 62.5mW; Voltage Rating: 50V
R32 = CMP-013-000022-9: RES SMD 0 OHM JUMPER 1/16W 0402; Manufacturer Part Number 1: CRCW04020000Z0ED; Manufacturer 1: Vishay; Voltage Rating: 50V; Power Rating: 63mW; Tolerance: 5%
R72 R73 = CMP-013-000013-8: RES SMD 2.2K OHM 1% 1/16W 0402; Manufacturer 1: Yageo; Power Rating: 63mW; Voltage Rating: 50V
TP26 TP34 TP35 = CMP-015-000000-1
U9 = BMI270: Accelerometer, Gyroscope, 6 Axis Sensor IÂ²C, SPI Output; Manufacturer 1: Bosch Sensortec
U11 = CMP-016-000000-1: IMU ACCEL/GYRO/MAG I2C 32BIT; Manufacturer 1: Hillcrest Laboratories; Sensor Type: Accelerometer,Gyroscope,Magnetometer; Output Type: SPI,I2C
Y1 = CMP-006-000001-2: CRYSTAL 32.768kHz ±20ppm Crystal 12.5pF 90 kOhms 2-SMD, No Lead; Manufacturer 1: Abracon

## Sheet EEPROM.SchDoc: =project_title
size Tabloid; PageSetup: Record=PageOptions¦CenterHorizontal=True¦CenterVertical=True¦PrintScale=0.73¦XCorrection=1.00¦YCorrection=1.00¦PrintKind=0¦BorderSize=5000000¦LeftOffset=0¦BottomOffset=0¦Orientation=2¦PaperLength=1000¦PaperWidth=1000¦Scale=100¦PaperSource=7¦PrintQuality=-4¦MediaType=1¦DitherType=10¦PaperKind=A4¦PrintScaleMode=1; CompanyName: Luxonis Holding; DrawnBy: Boris Chou / Blaz Kvas; Organization: Luxonis Holding; Address1: 1925 Harmony Park Drive; Address2: Westminster, CO; Address3: 80234; Address4: United States; DocumentNumber: D2088000; Revision: R1M1E1; SheetNumber: 8; SheetTotal: 12
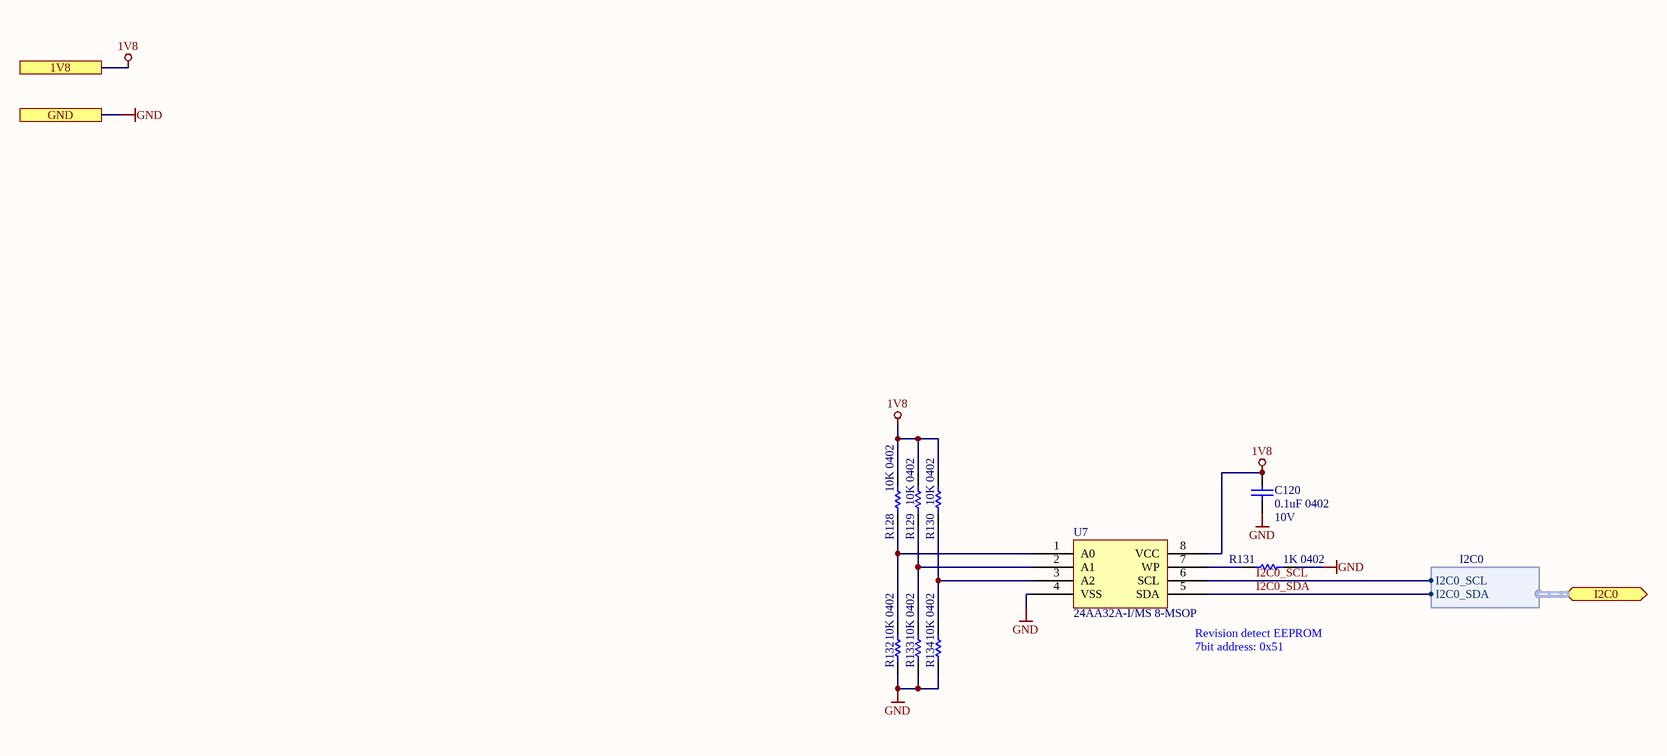
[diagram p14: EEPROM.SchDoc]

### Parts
C120  0.1uF 0402  Voltage Rating: 10V  [CAPC0402(1005)70_L]
R128  10K 0402  [RESC0402(1005)_L]
R129  10K 0402  [RESC0402(1005)_L]
R130  10K 0402  [RESC0402(1005)_L]
R131  1K 0402  [RESC0402(1005)_L]
R132  10K 0402  [RESC0402(1005)_L]
R133  10K 0402  [RESC0402(1005)_L]
R134  10K 0402  [RESC0402(1005)_L]
U7  24AA32A-I/MS 8-MSOP  [24AA32A-I/MS]

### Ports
1V8, GND, I2C0 (bidir, harness I2C0)

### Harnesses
I2C0: I2C0_SCL, I2C0_SDA

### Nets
1V8: C120.2 R128.2 R129.2 R130.2 U7.8(VCC) ; port 1V8
GND: C120.1 R131.1 R132.1 R133.1 R134.1 U7.4(VSS) ; port GND
I2C0_SCL: U7.6(SCL) ; port I2C0.I2C0_SCL
I2C0_SDA: U7.5(SDA) ; port I2C0.I2C0_SDA
NetR128_1: R128.1 R132.2 U7.1(A0)
NetR129_1: R129.1 R133.2 U7.2(A1)
NetR130_1: R130.1 R134.2 U7.3(A2)
NetR131_2: R131.2 U7.7(WP)

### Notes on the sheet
- (near U7) Revision detect EEPROM
- (near U7) 7bit address: 0x51

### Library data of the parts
C120 = GRM155R71A104JA01D: as C69 on sheet MID_AR0234
R128-R130 R132-R134 = RC0402FR-1310KL: as R54 on sheet MID_AR0234
R131 = RC0402FR-071KL: RES SMD 1K OHM 1% 1/16W 0402; Manufacturer 1: Yageo; Temperature Coefficient: 100ppm/°C; Power Rating: 62.5mW; Voltage Rating (DC): 50V; Resistance: 1kR
U7 = 24AA32A-I/MS: IC EEPROM 32K I2C 400KHZ 8MSOP Memory IC 32Kb (4K x 8) I²C 400kHz 900ns 8-MSOP; Manufacturer 1: Microchip; Interface: I2C,Serial,2-Wire; Access Time: 3500ns; Max Supply Voltage: 5.5V; Min Supply Voltage: 1.7V; Nominal Supply Current: 3mA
